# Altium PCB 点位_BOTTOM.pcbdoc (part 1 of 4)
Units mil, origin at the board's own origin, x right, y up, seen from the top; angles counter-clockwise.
Board outline 5102.8 x 4152 mil, 8 copper layers (Top Layer, GND1, 内层2, VCC, 内层4, Inner5, GND2, Bottom Layer); 209 components, 325 nets, 527 pads, 1119 vias.
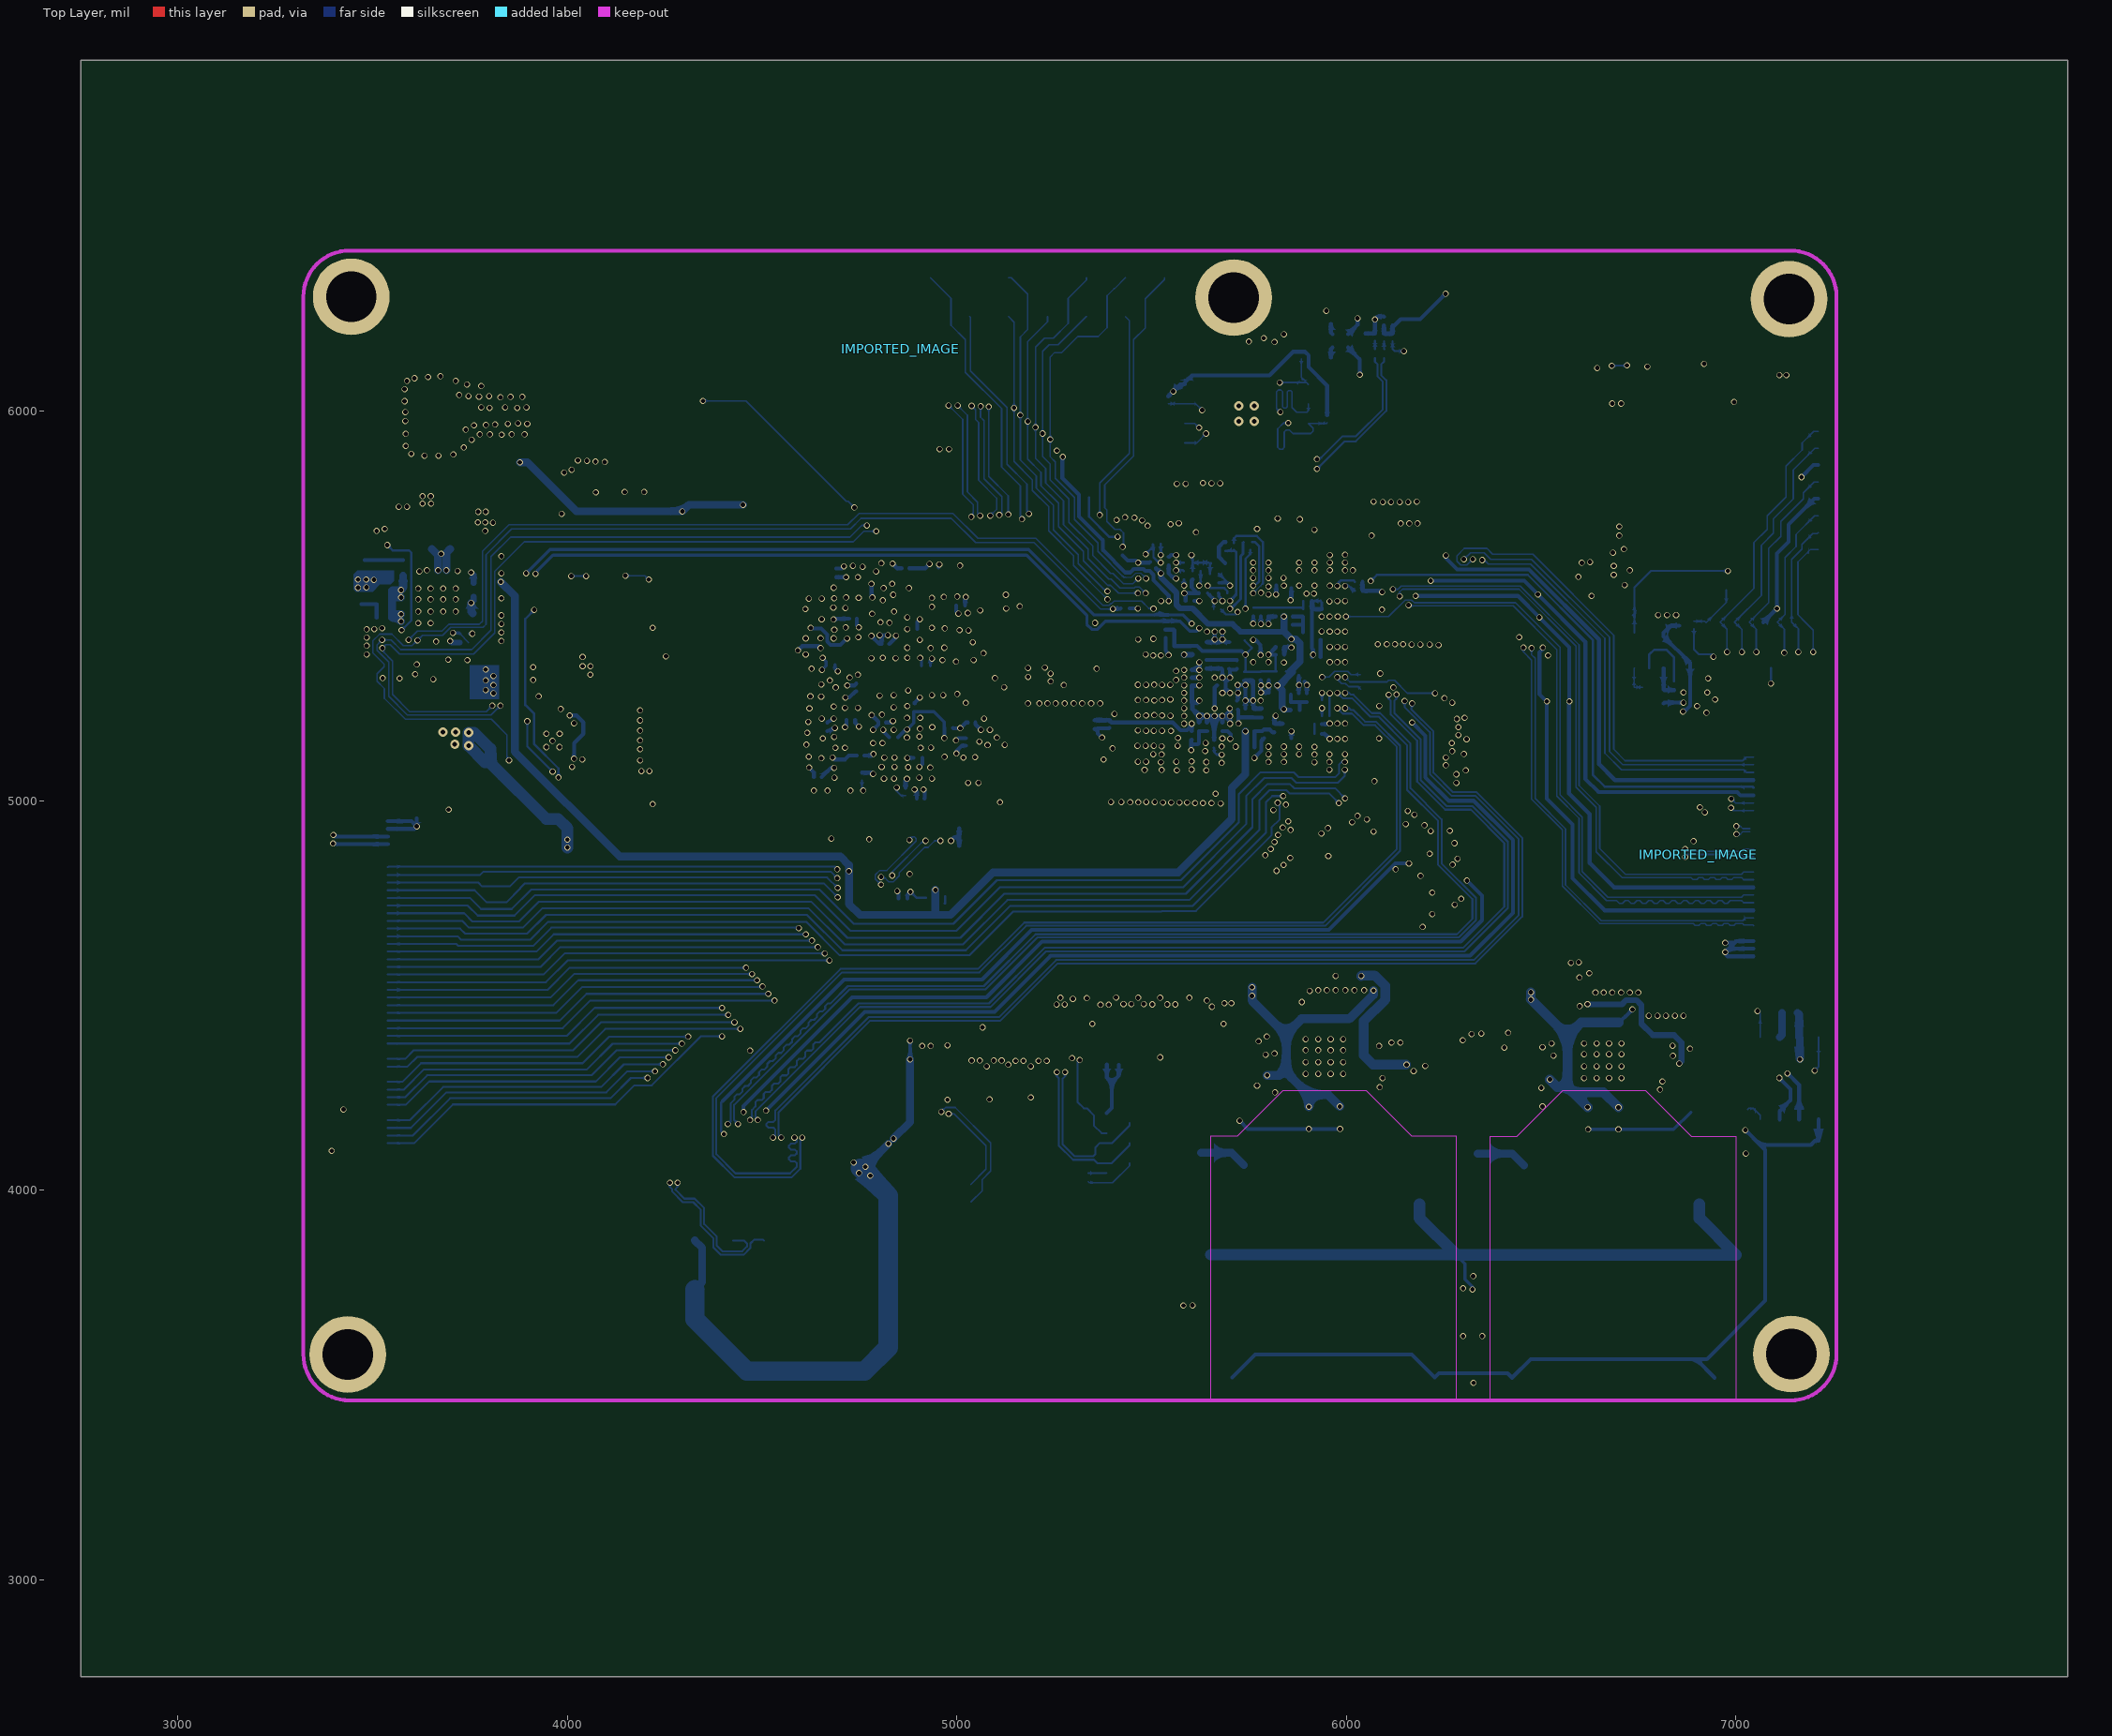
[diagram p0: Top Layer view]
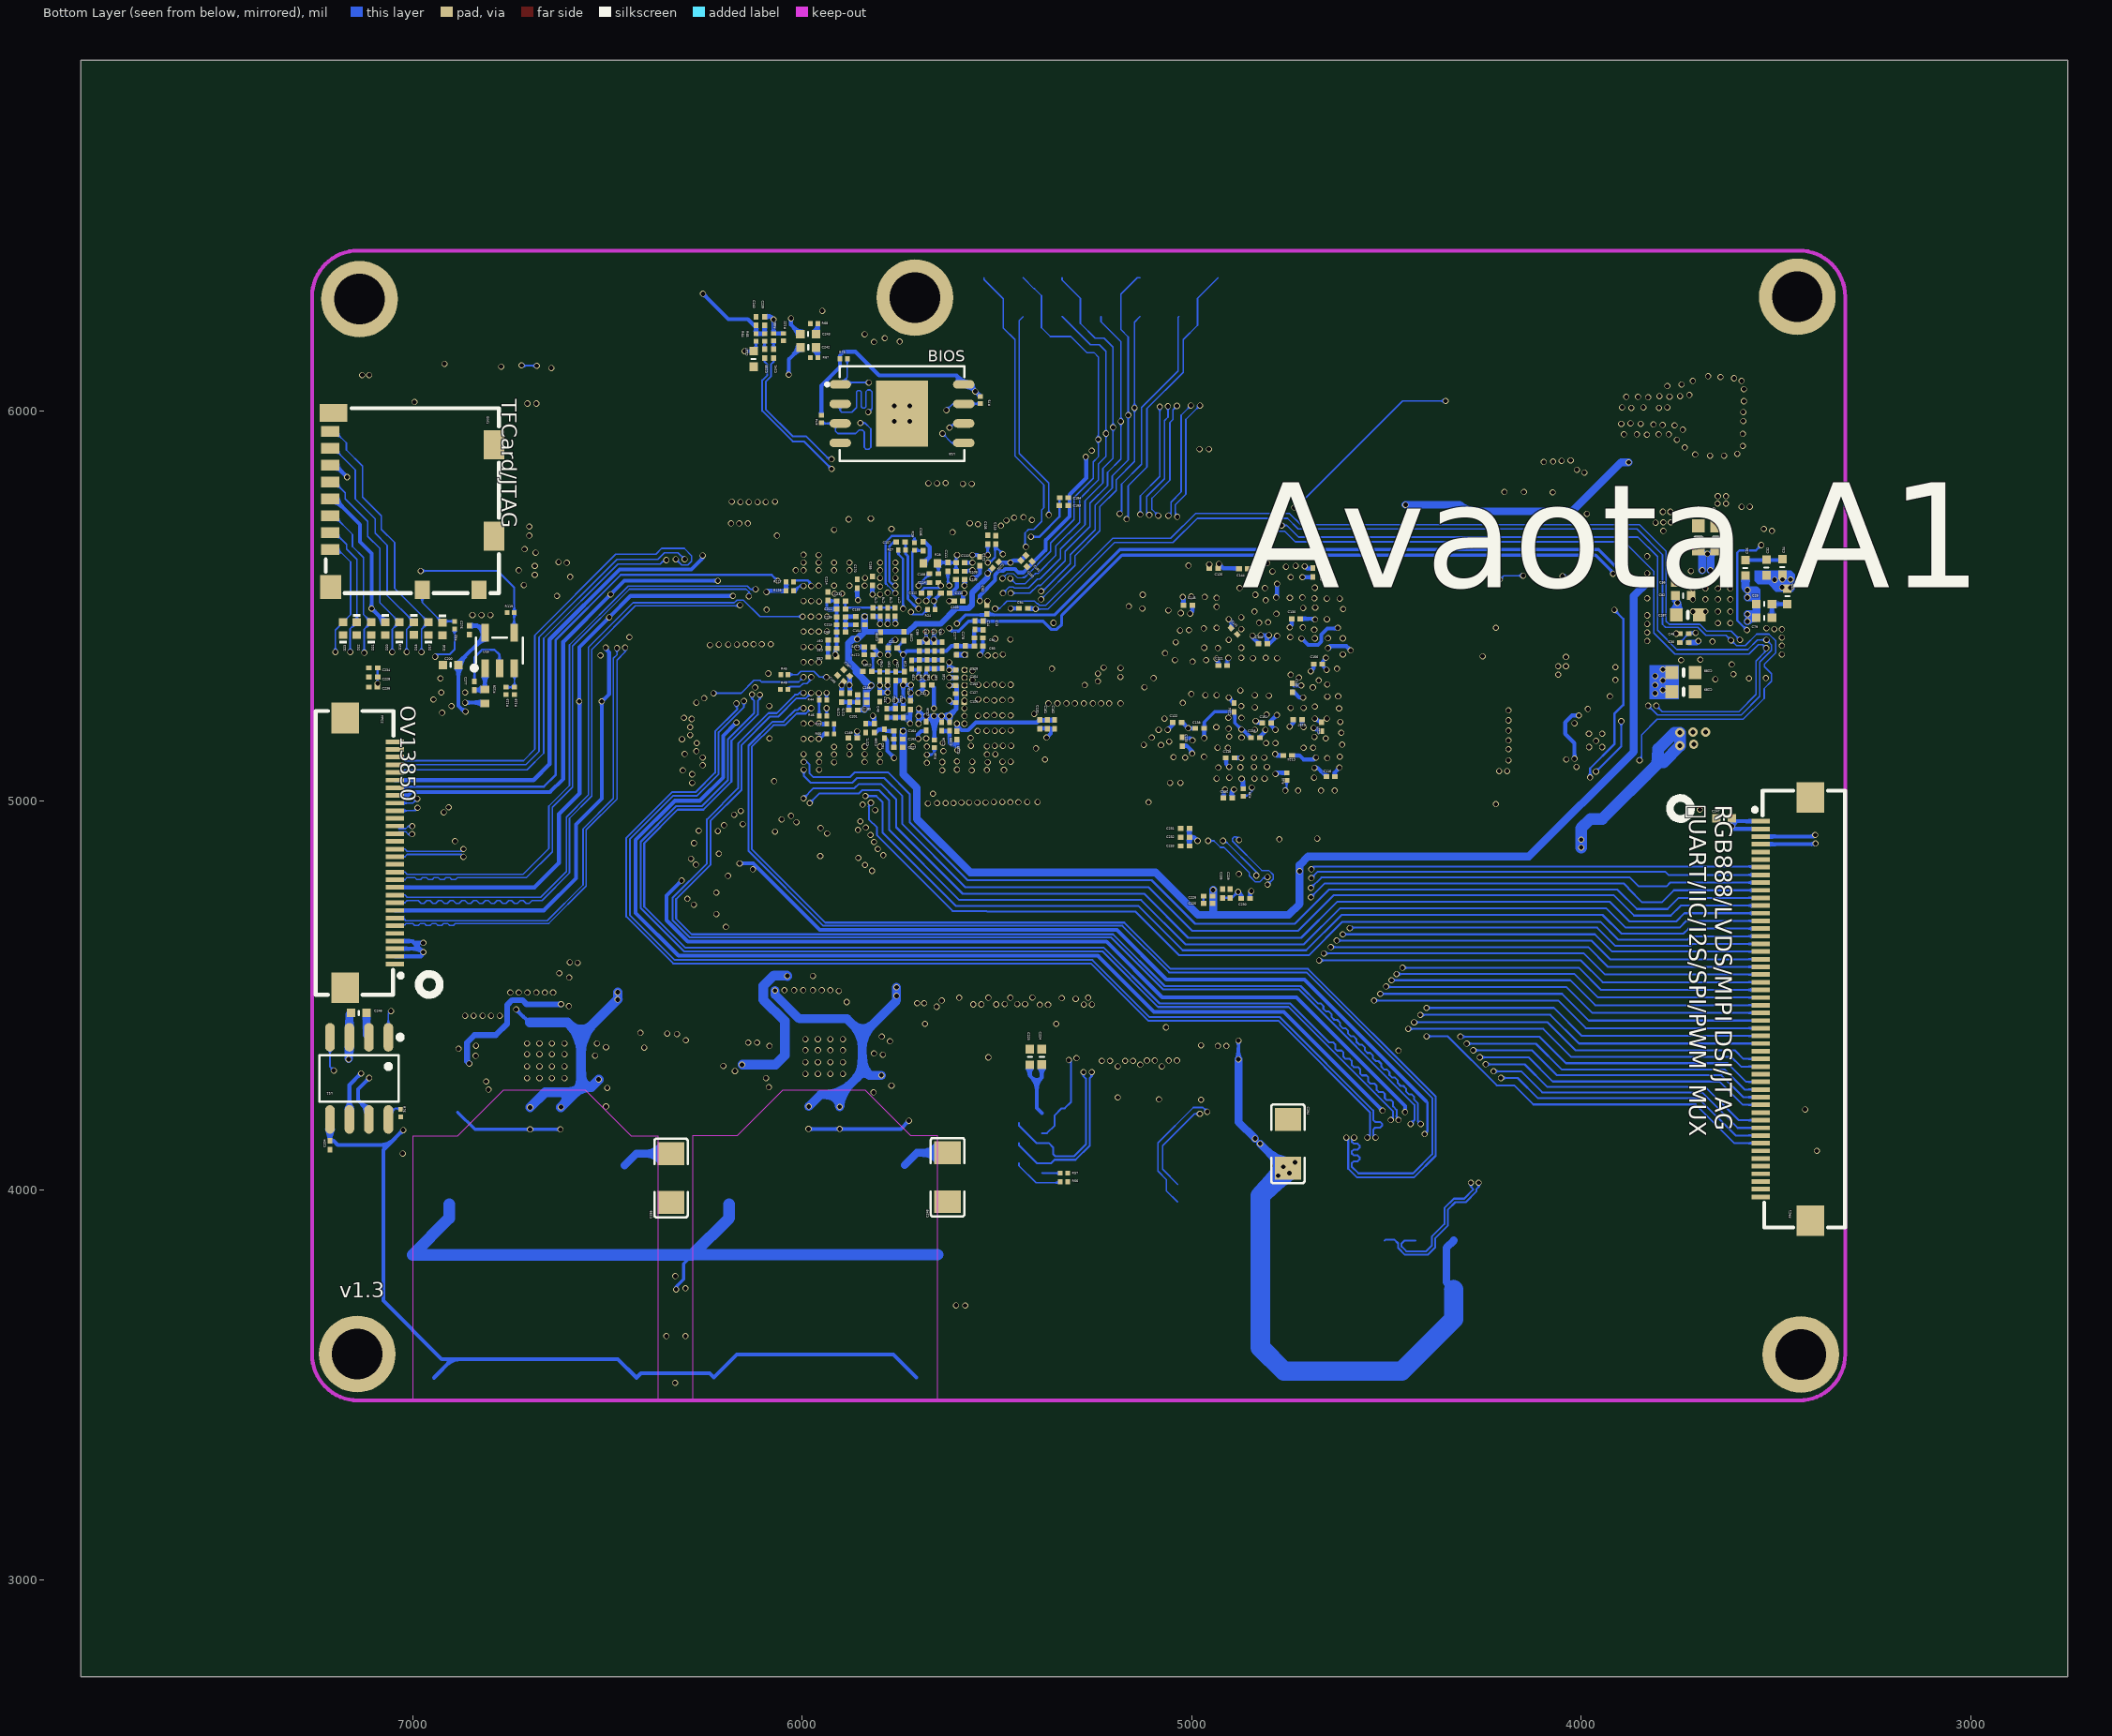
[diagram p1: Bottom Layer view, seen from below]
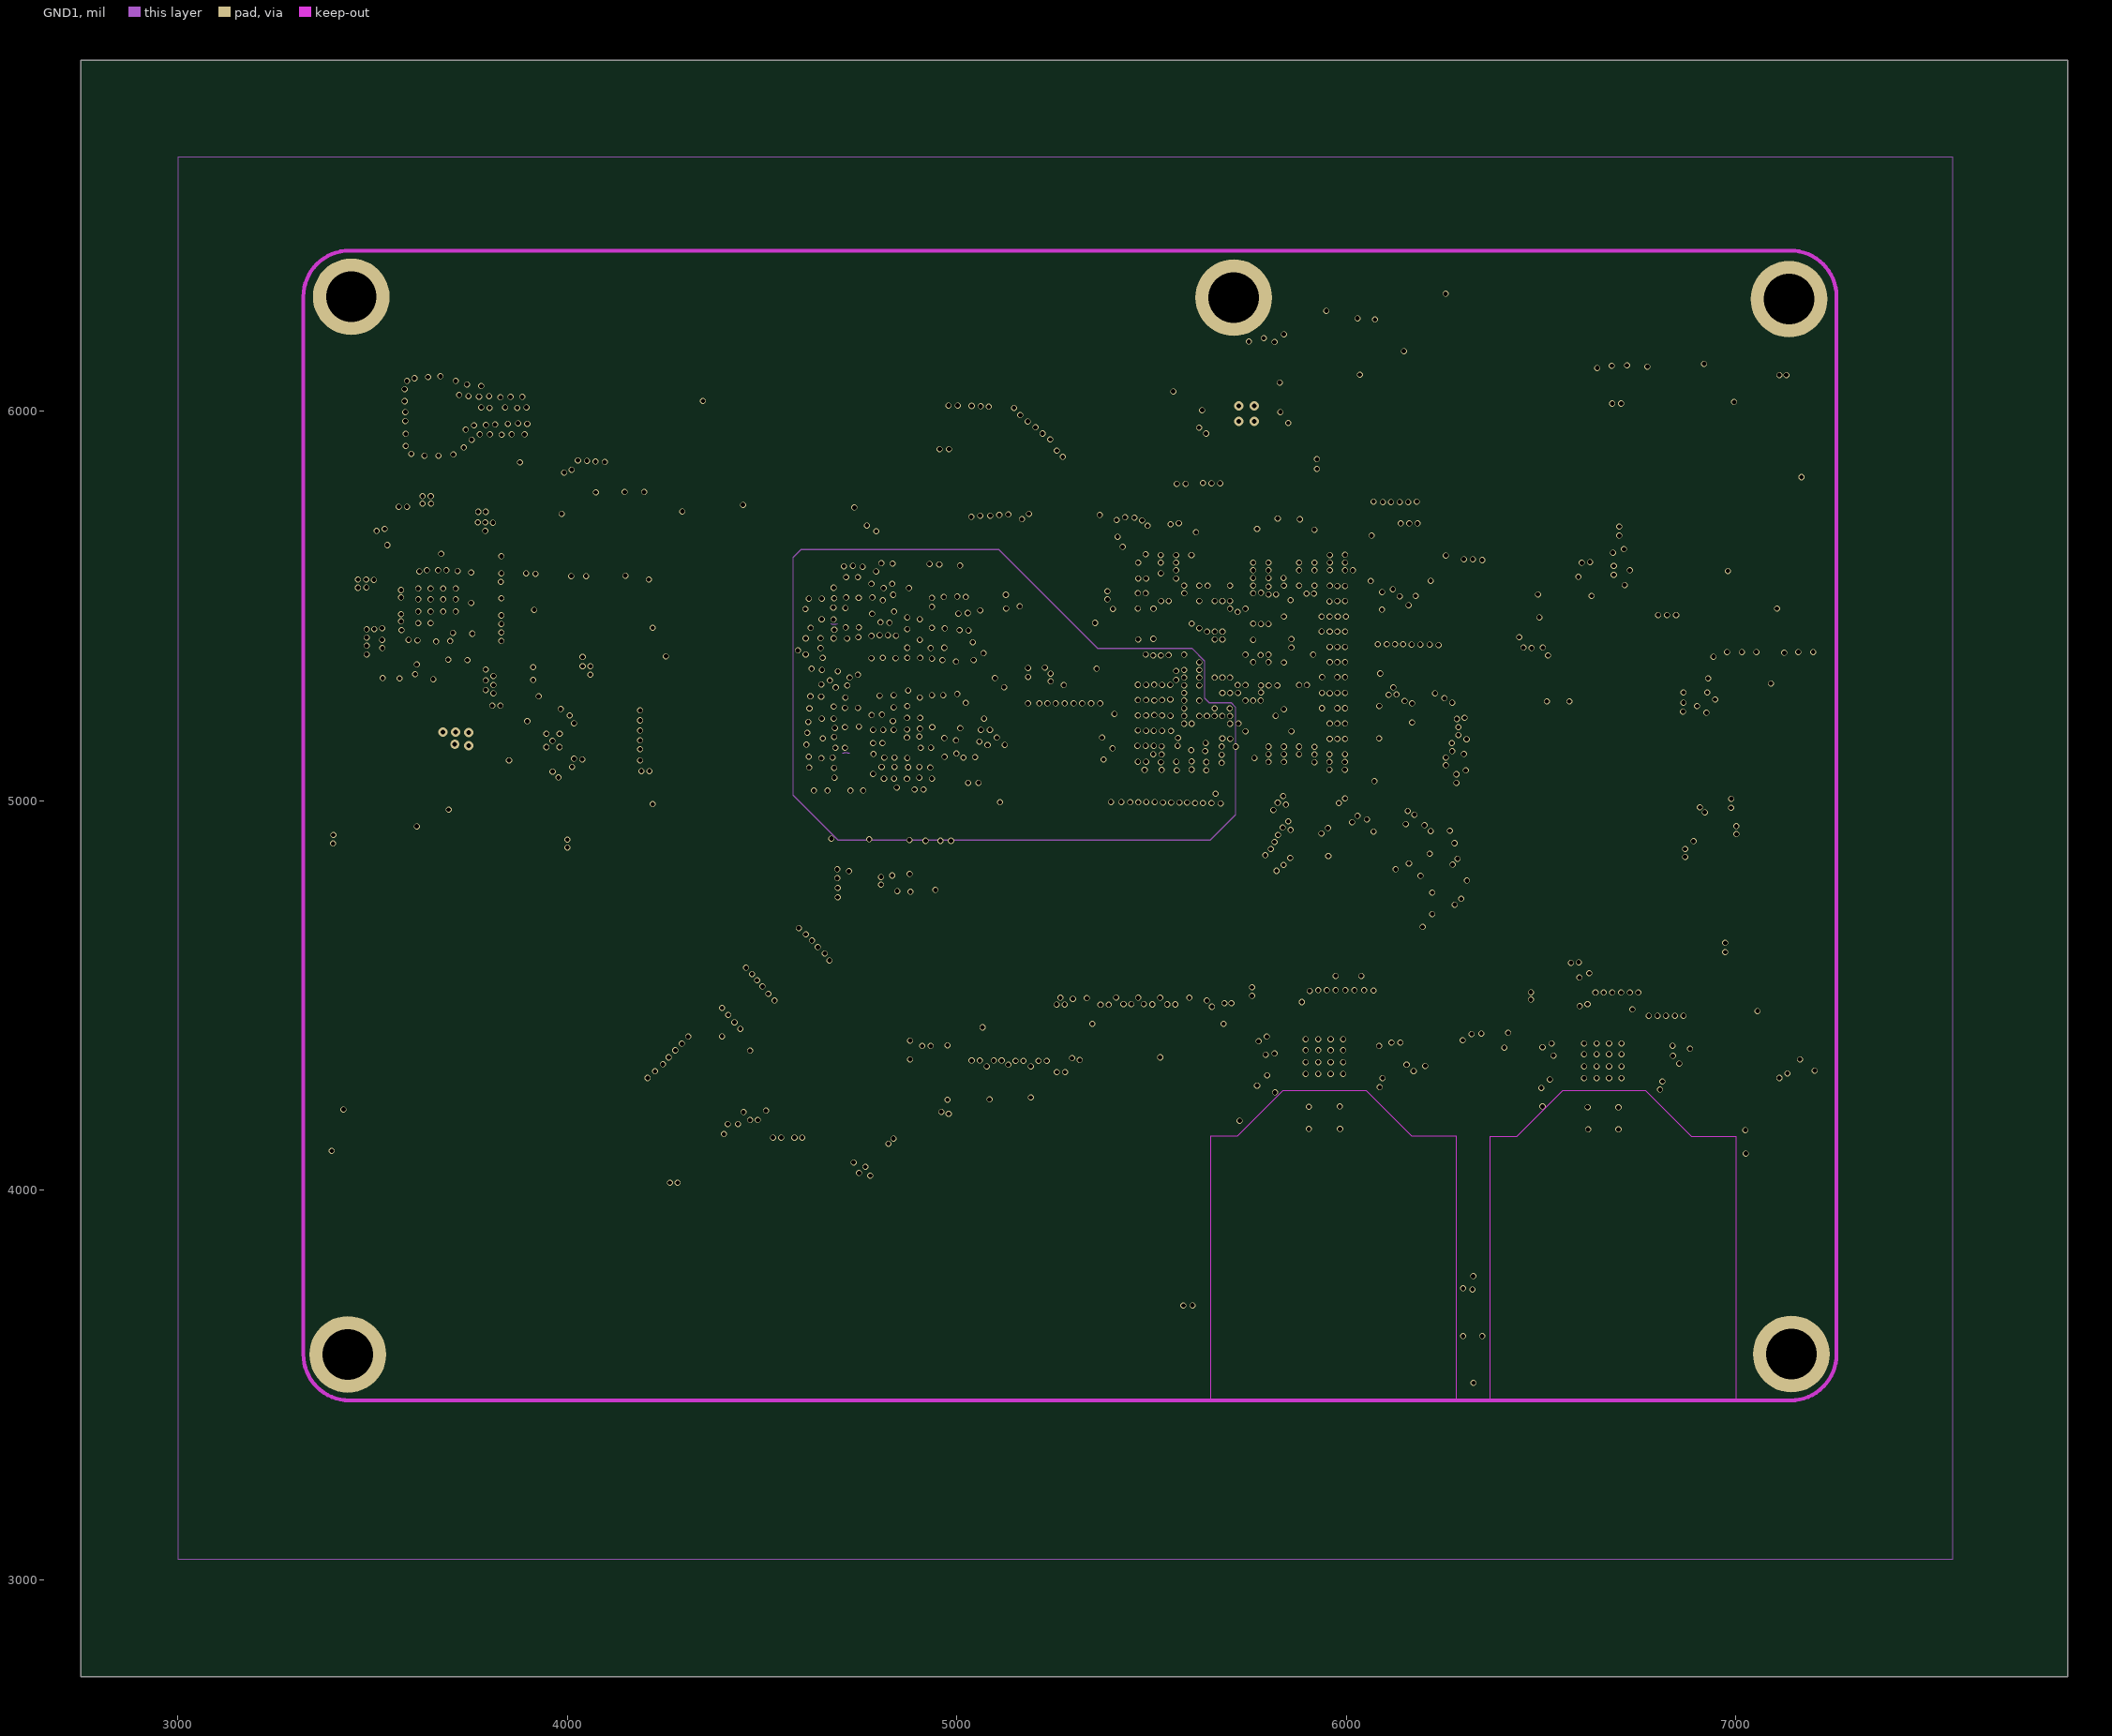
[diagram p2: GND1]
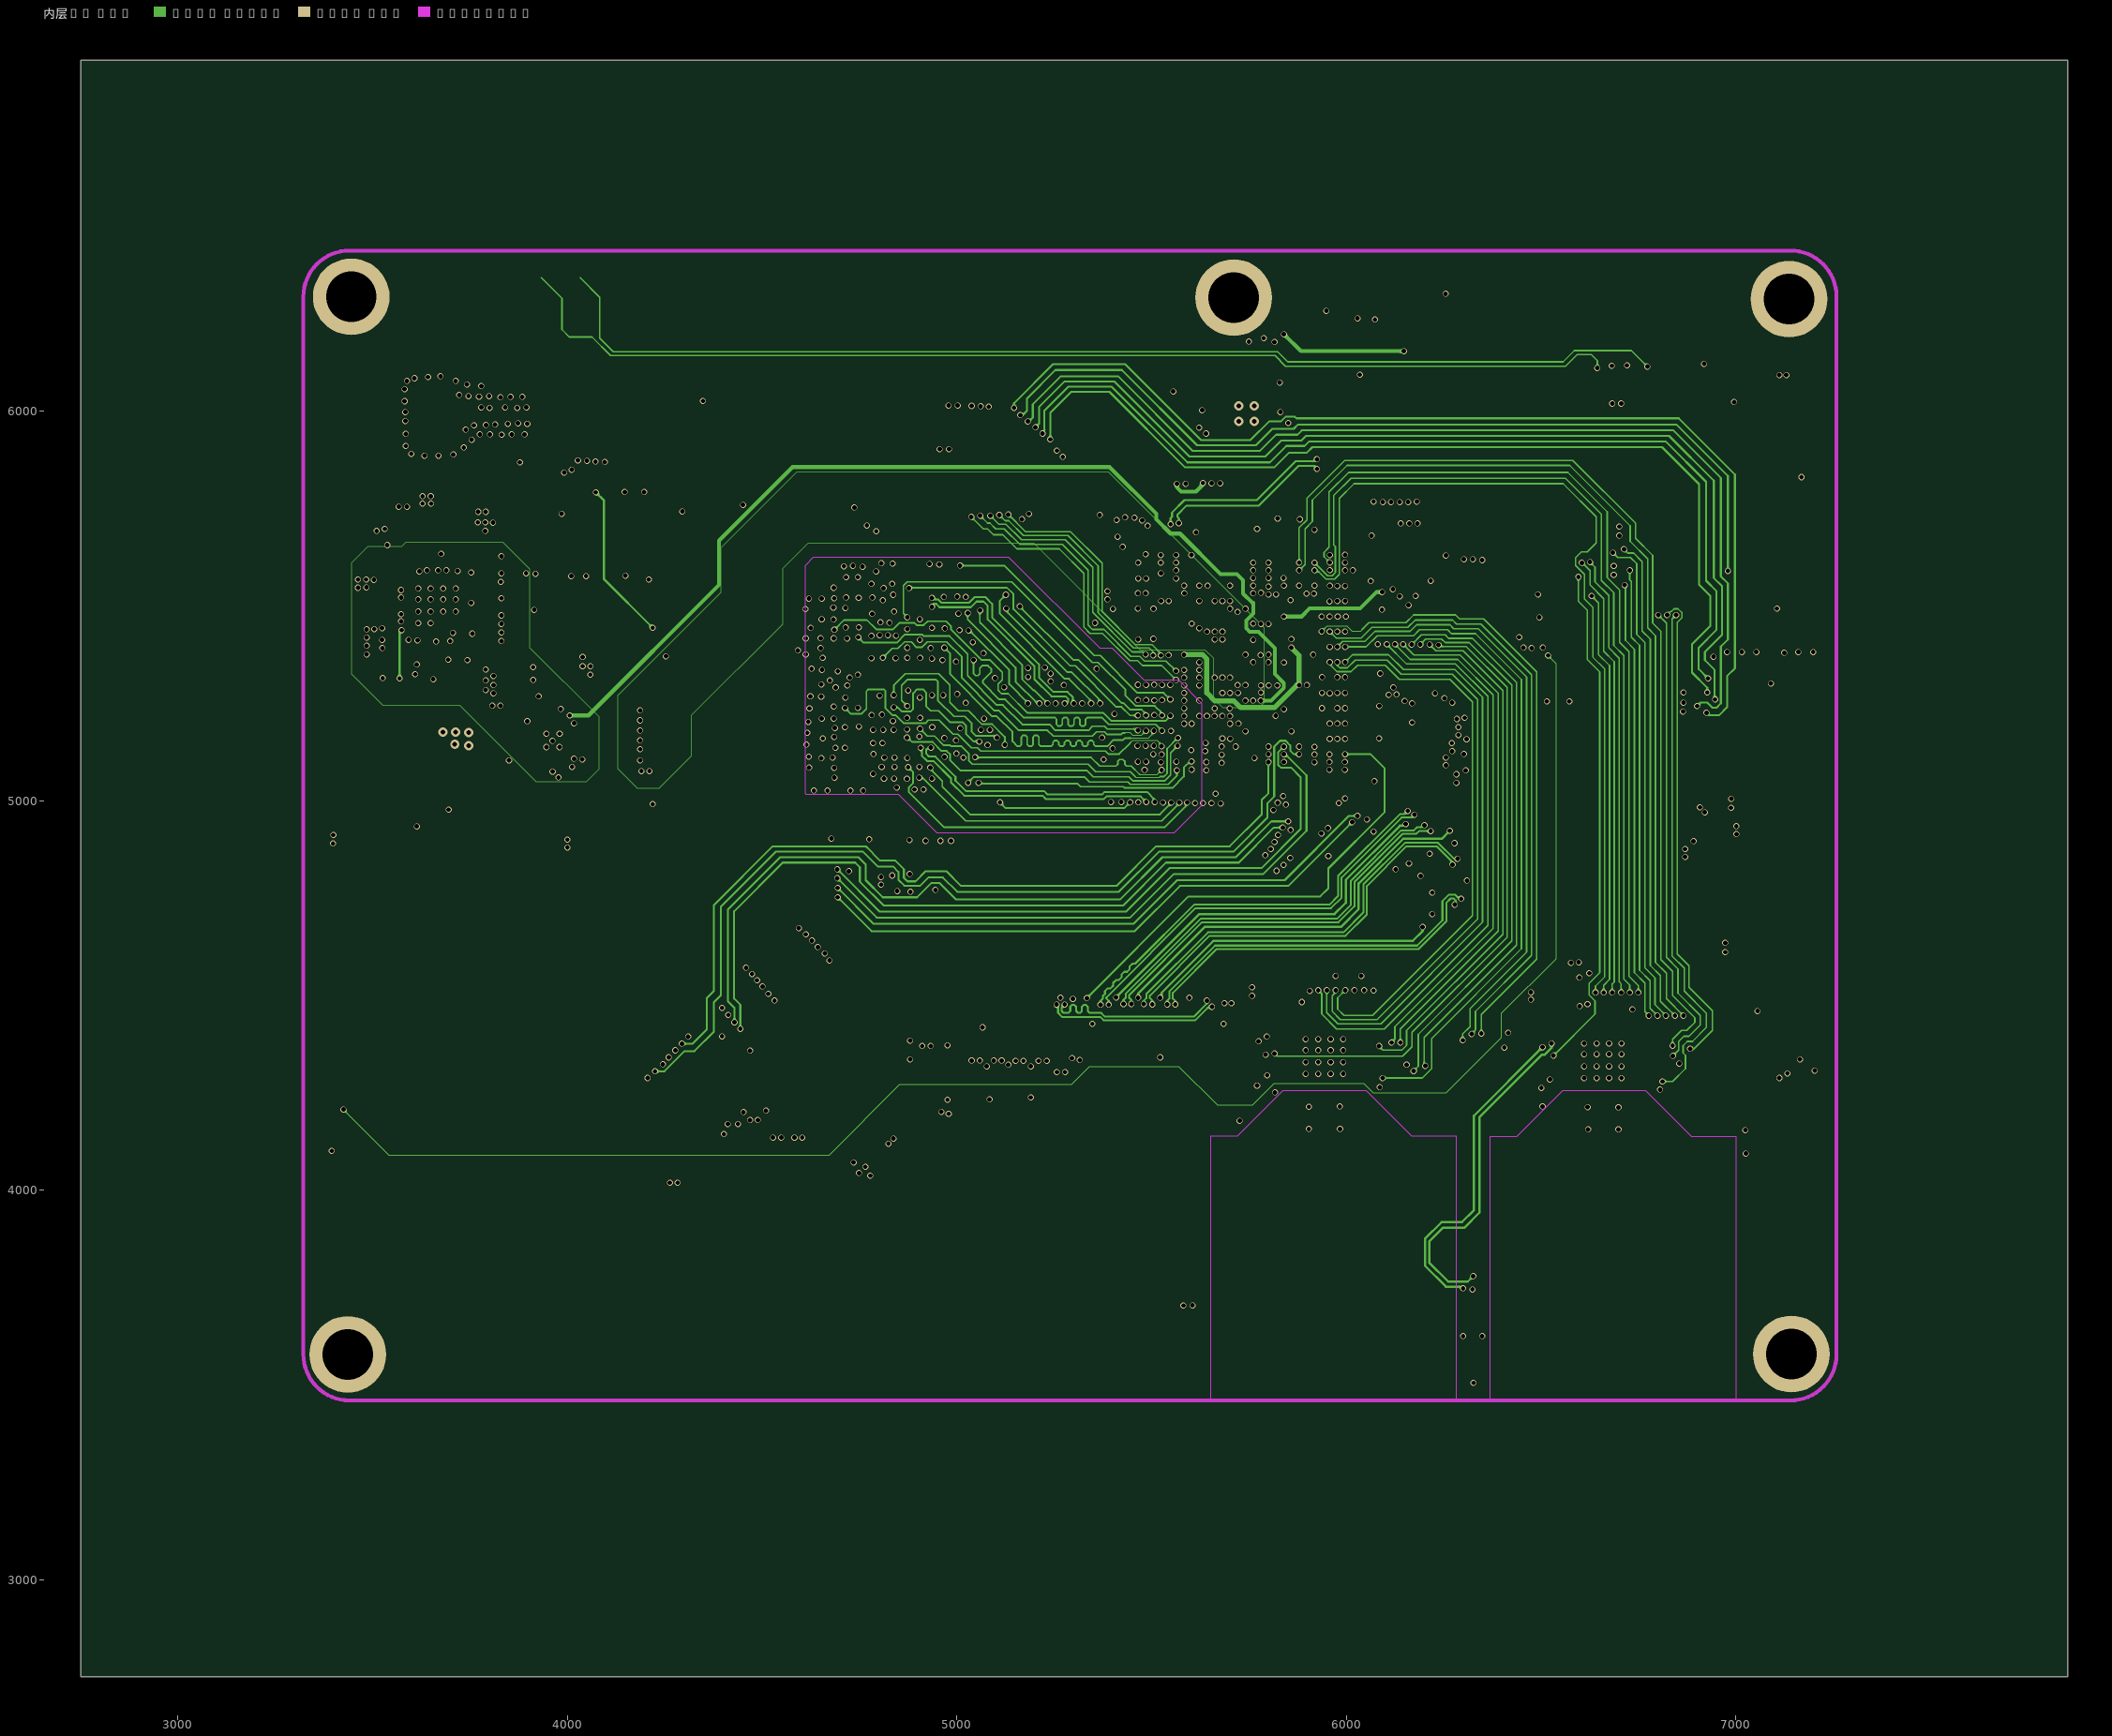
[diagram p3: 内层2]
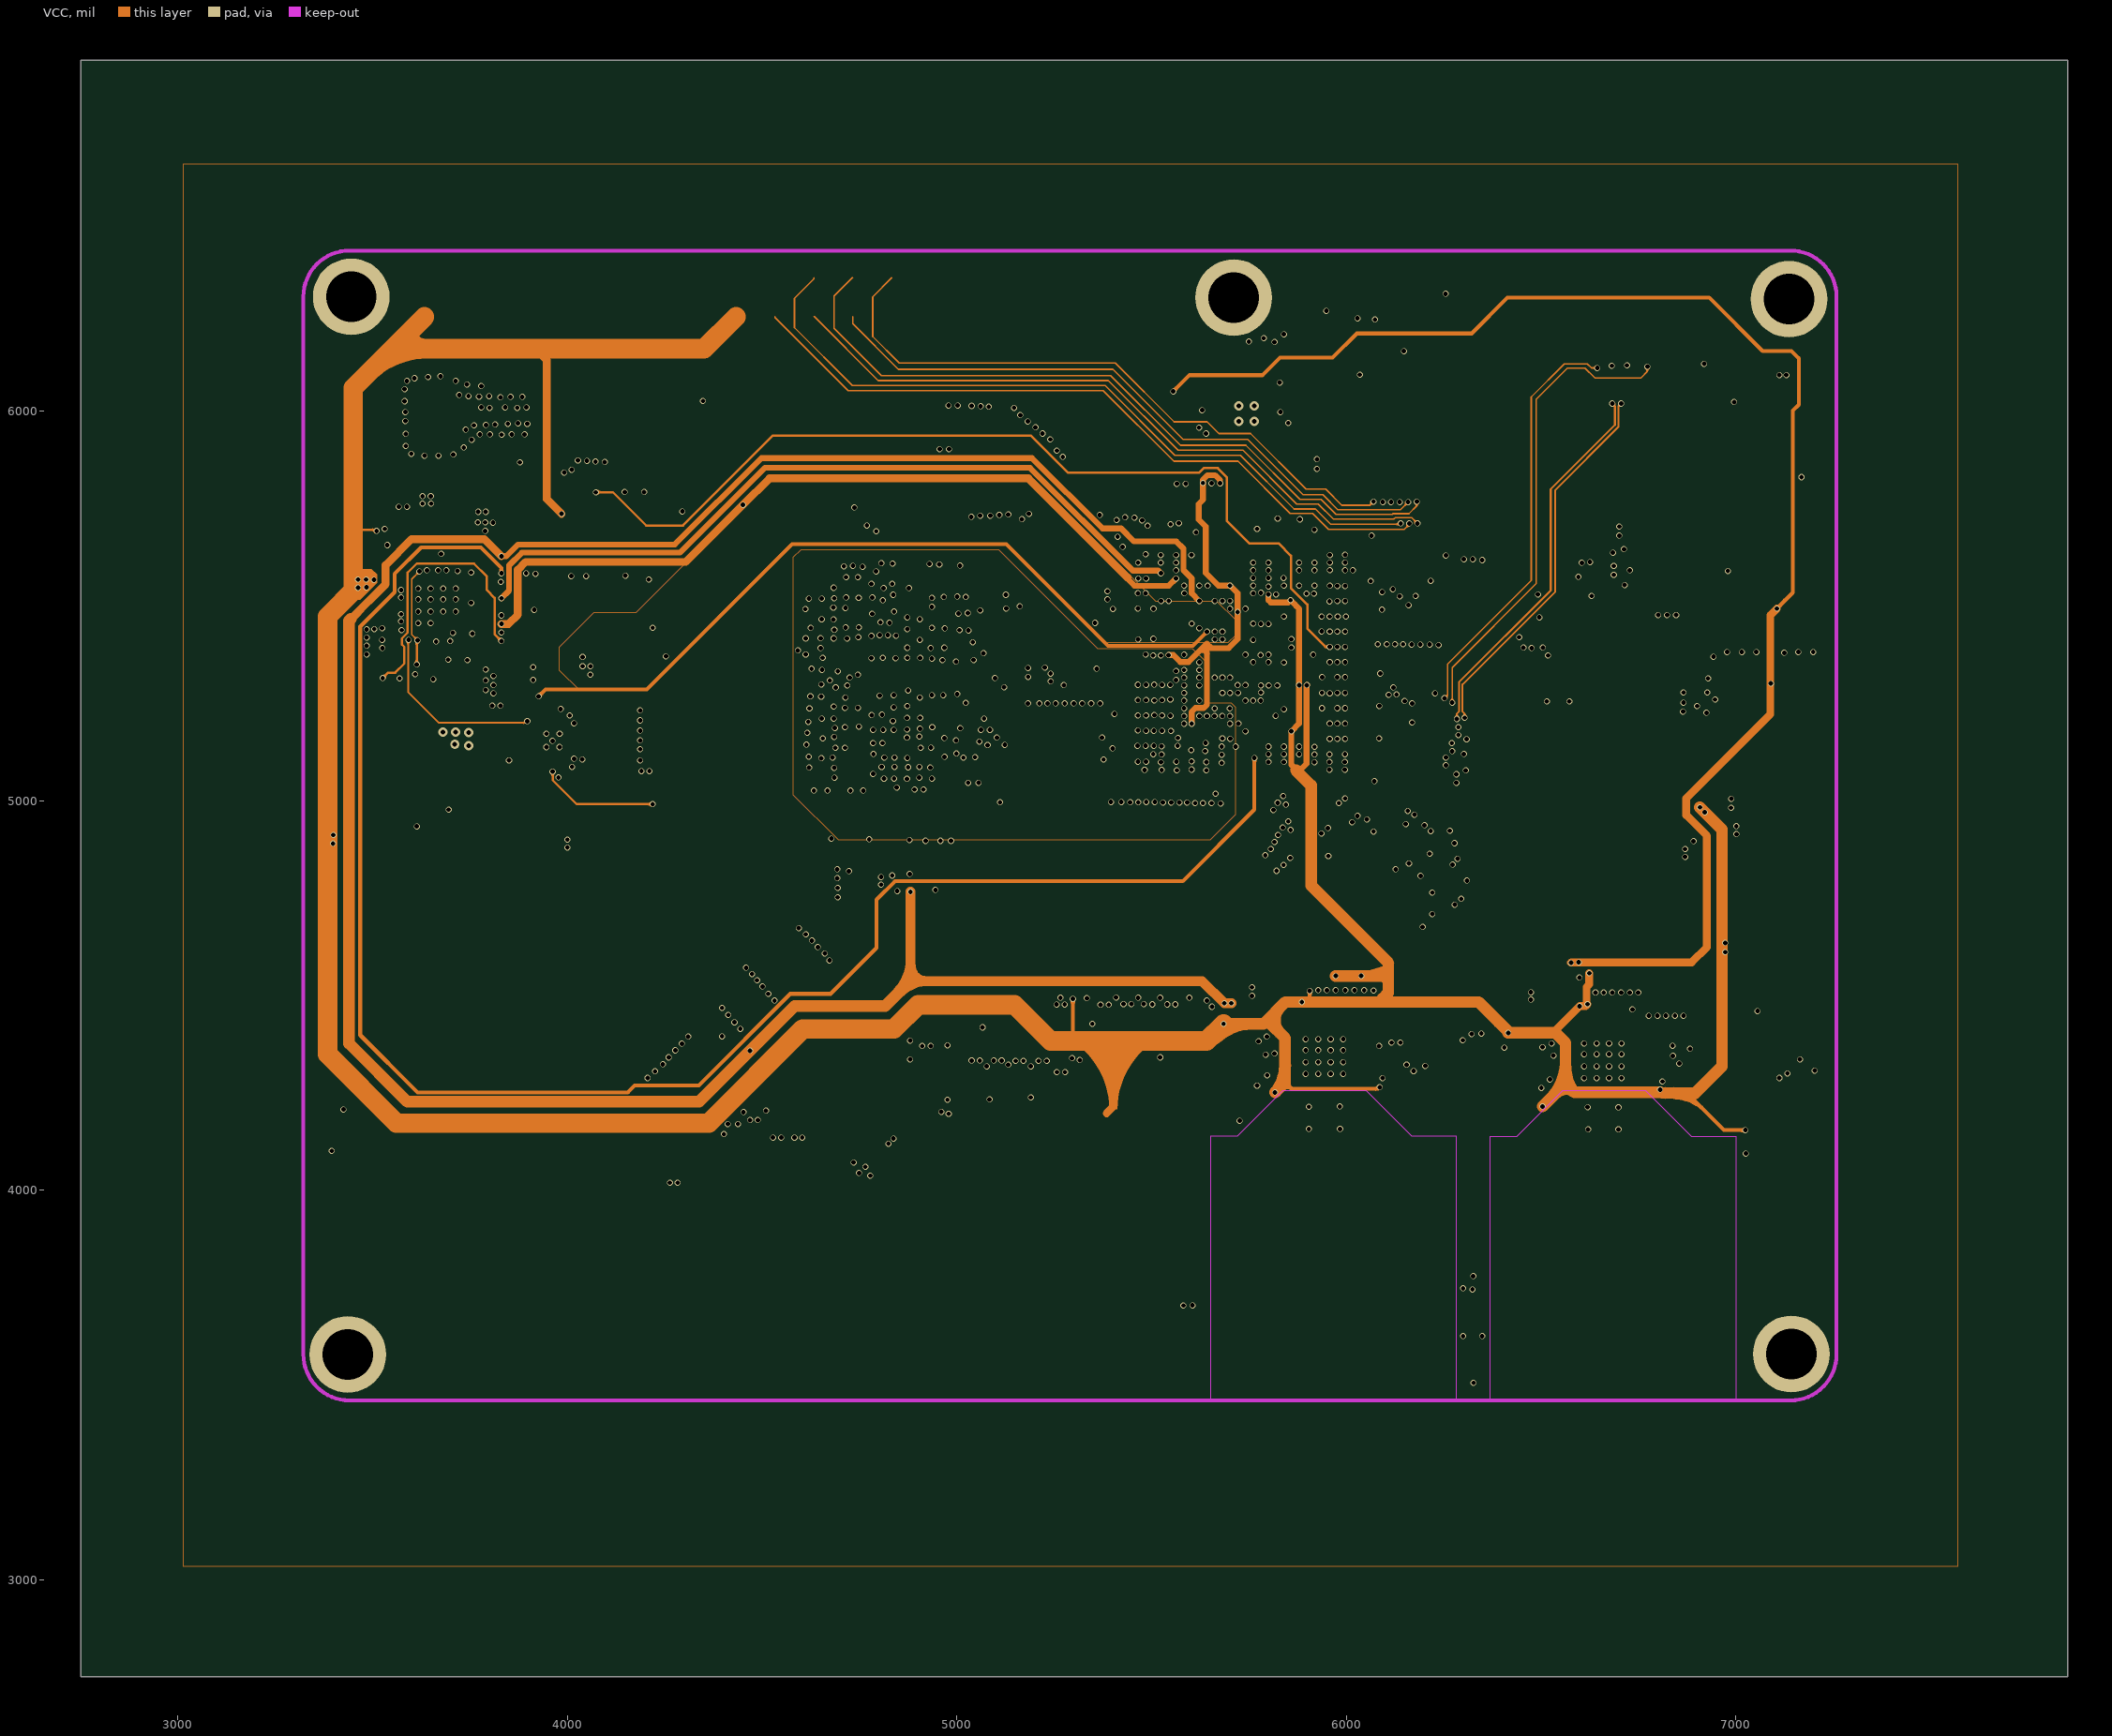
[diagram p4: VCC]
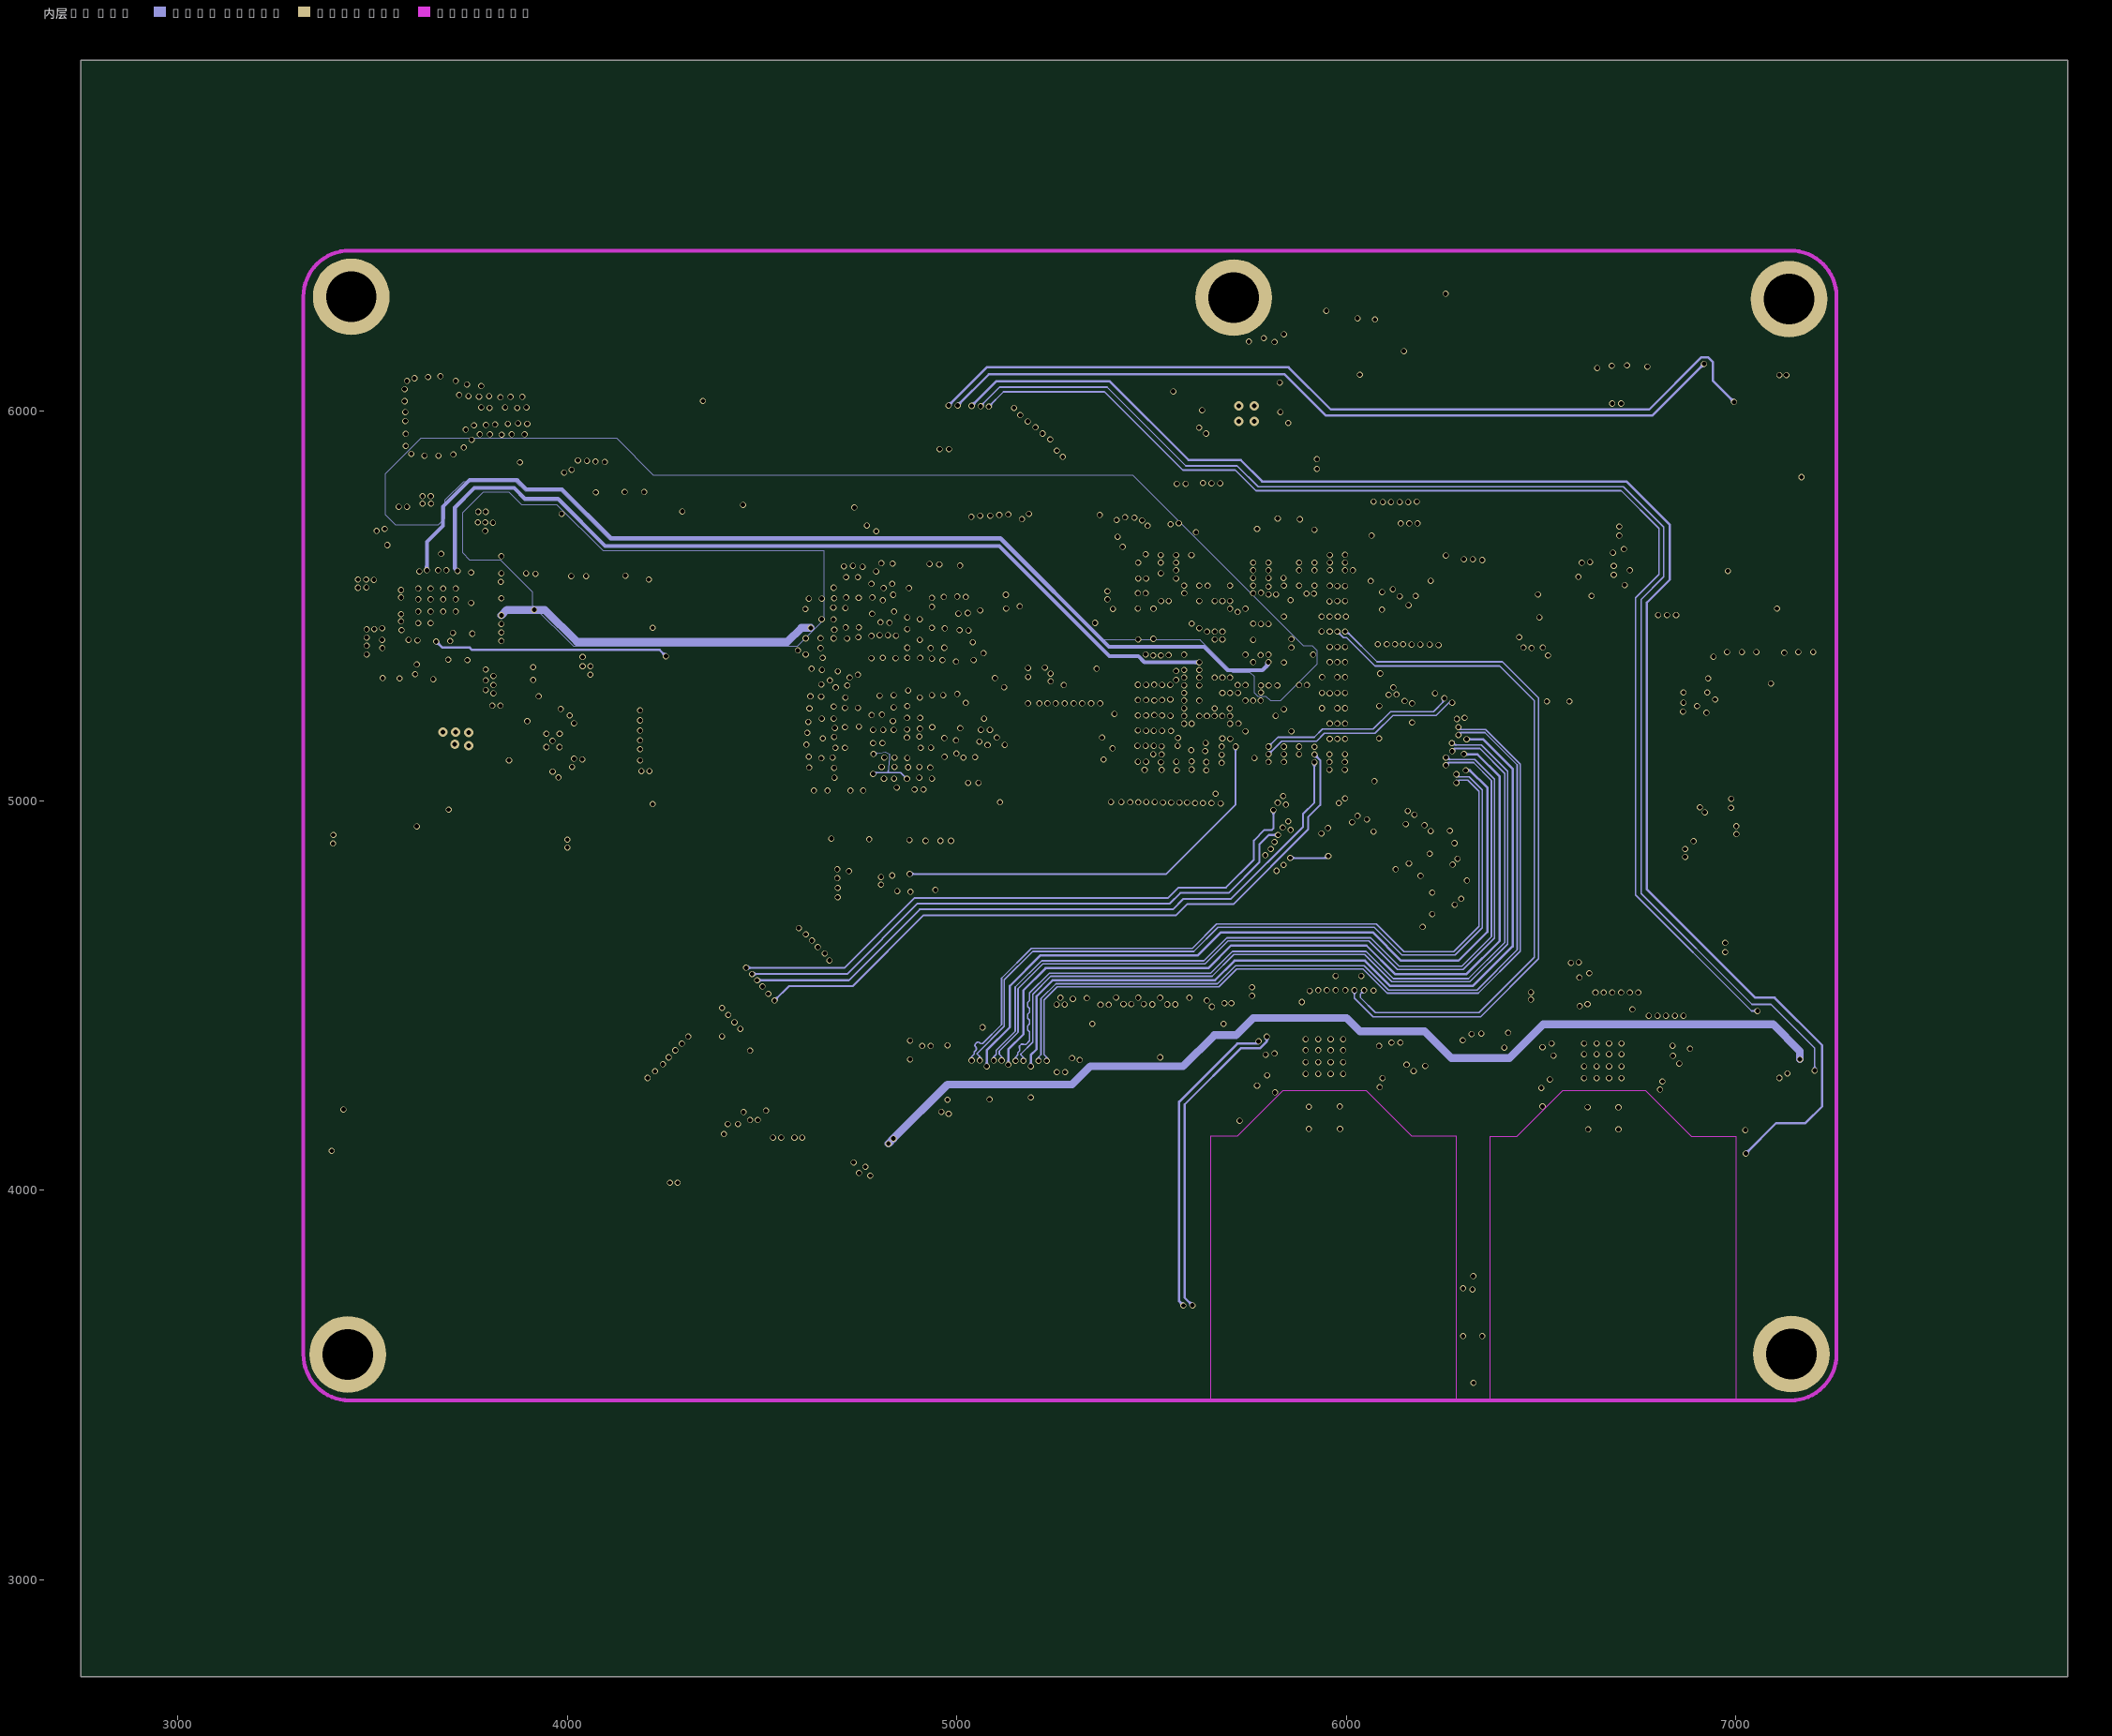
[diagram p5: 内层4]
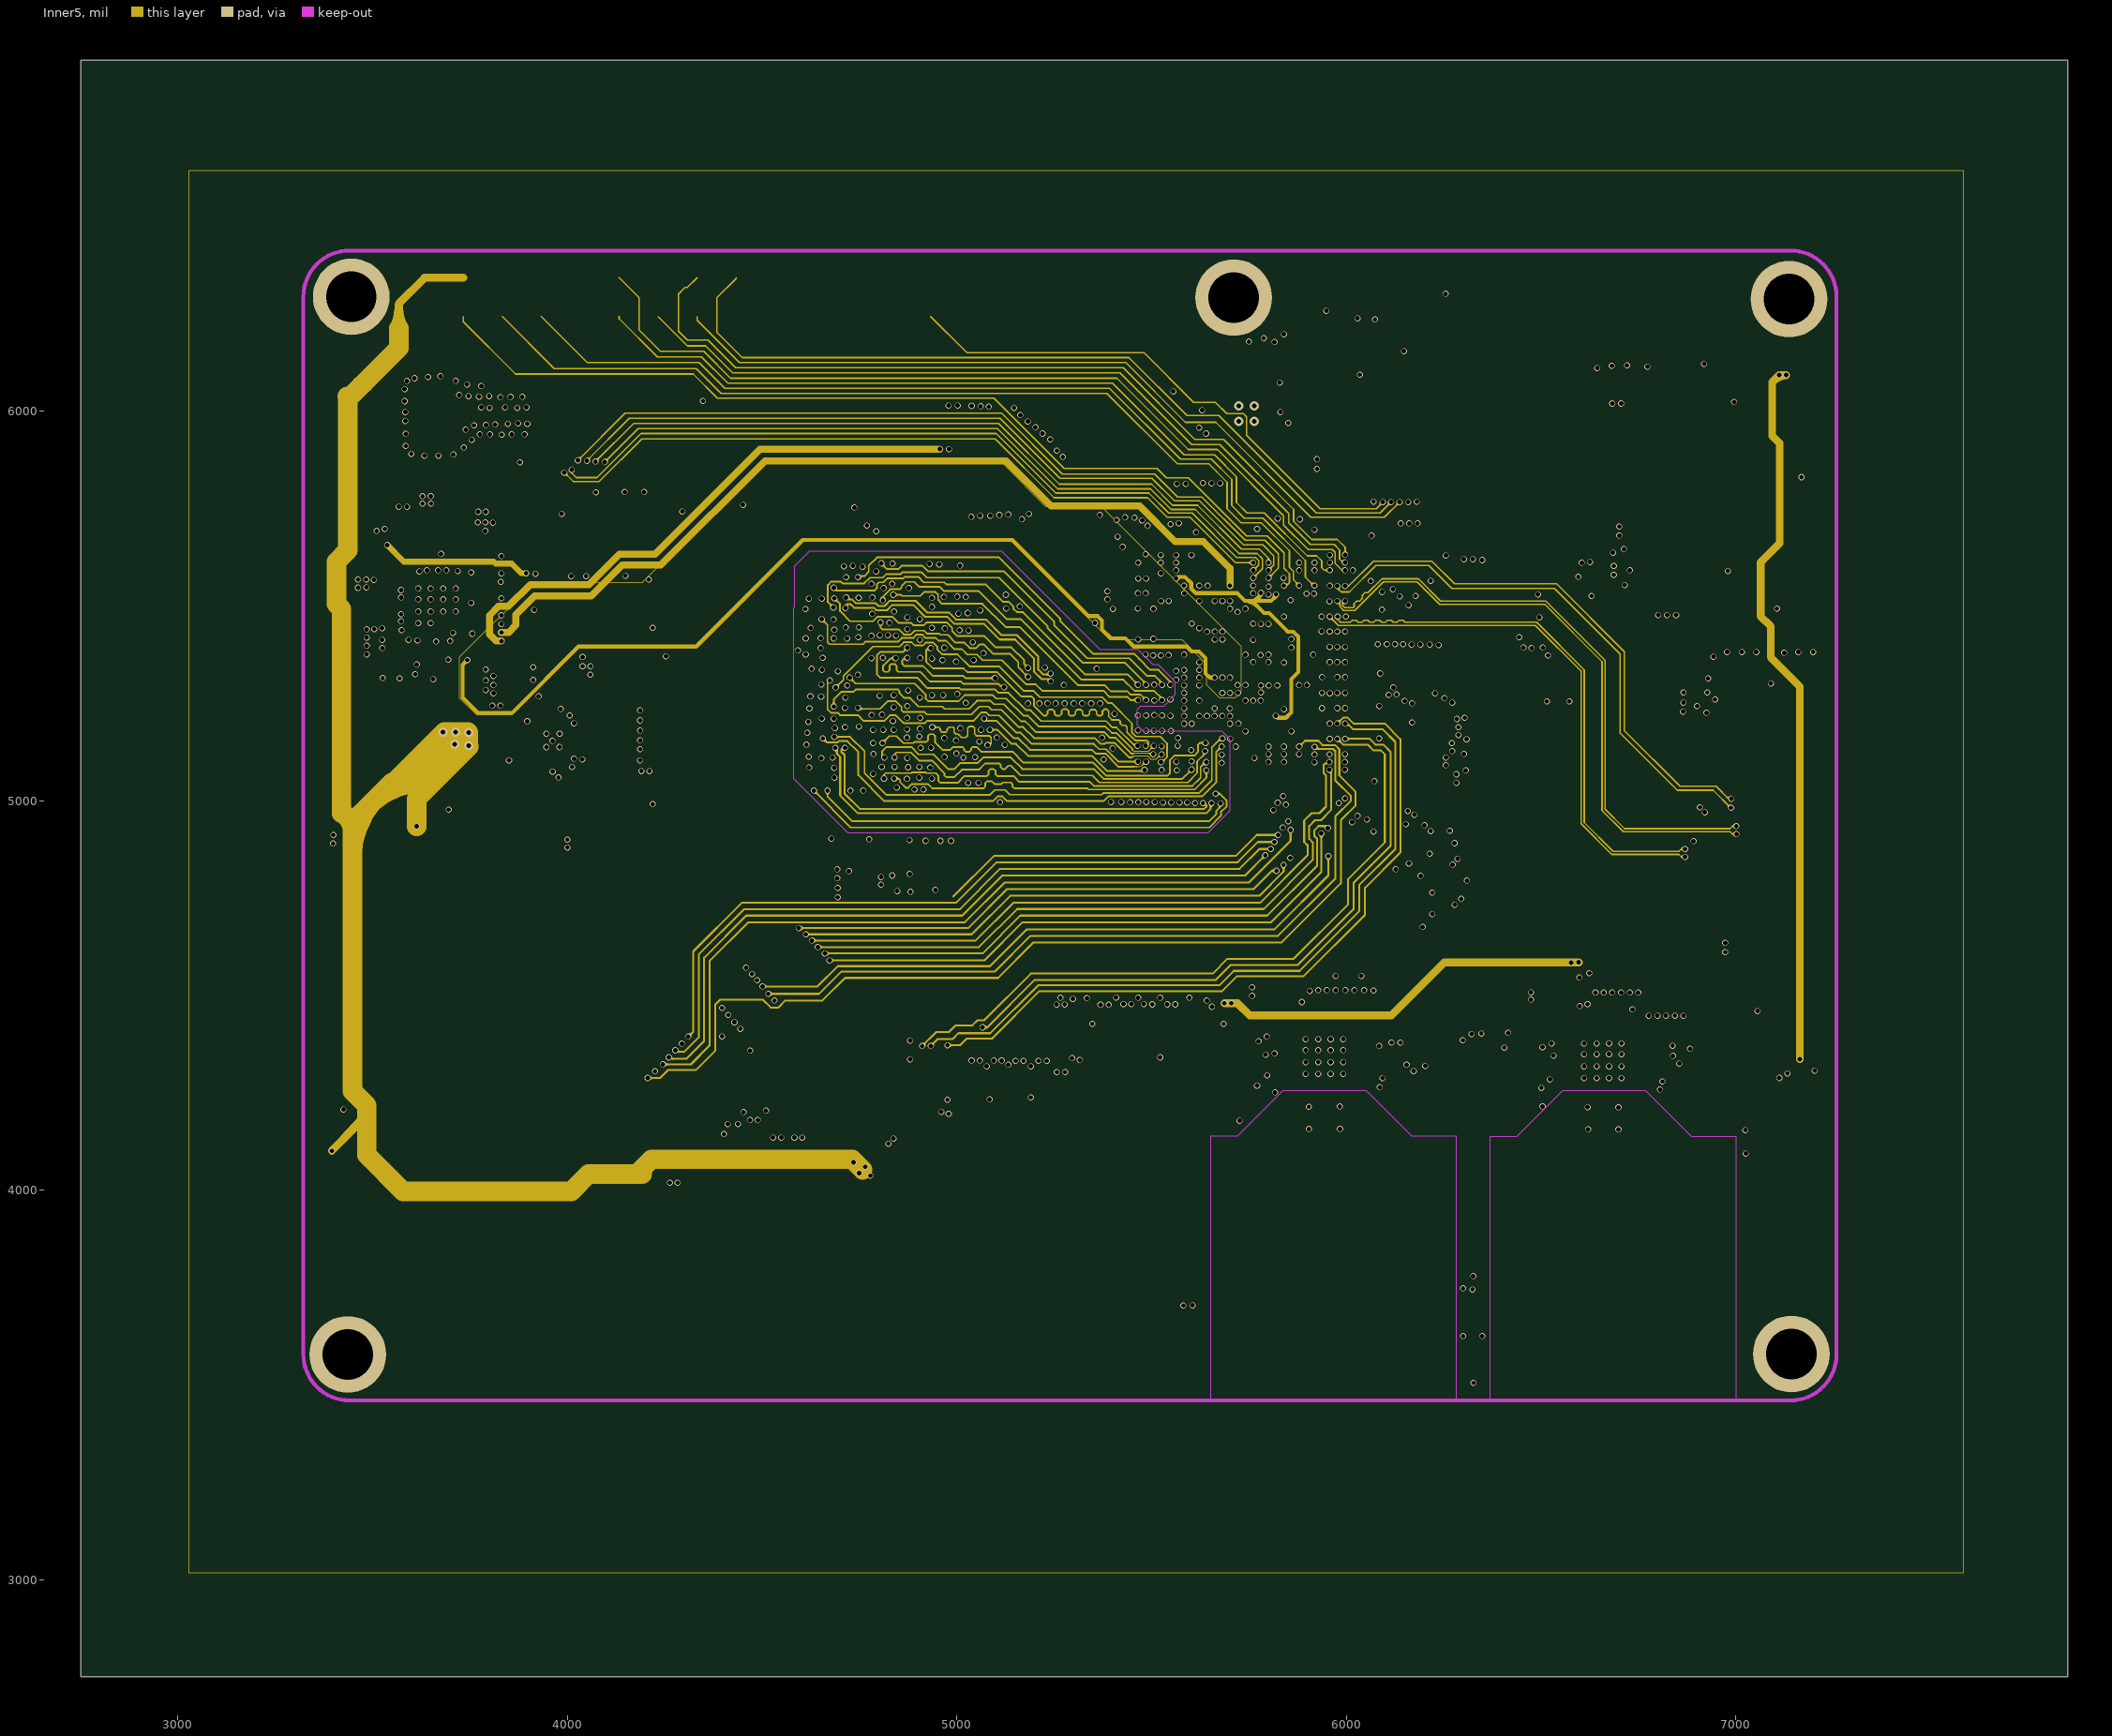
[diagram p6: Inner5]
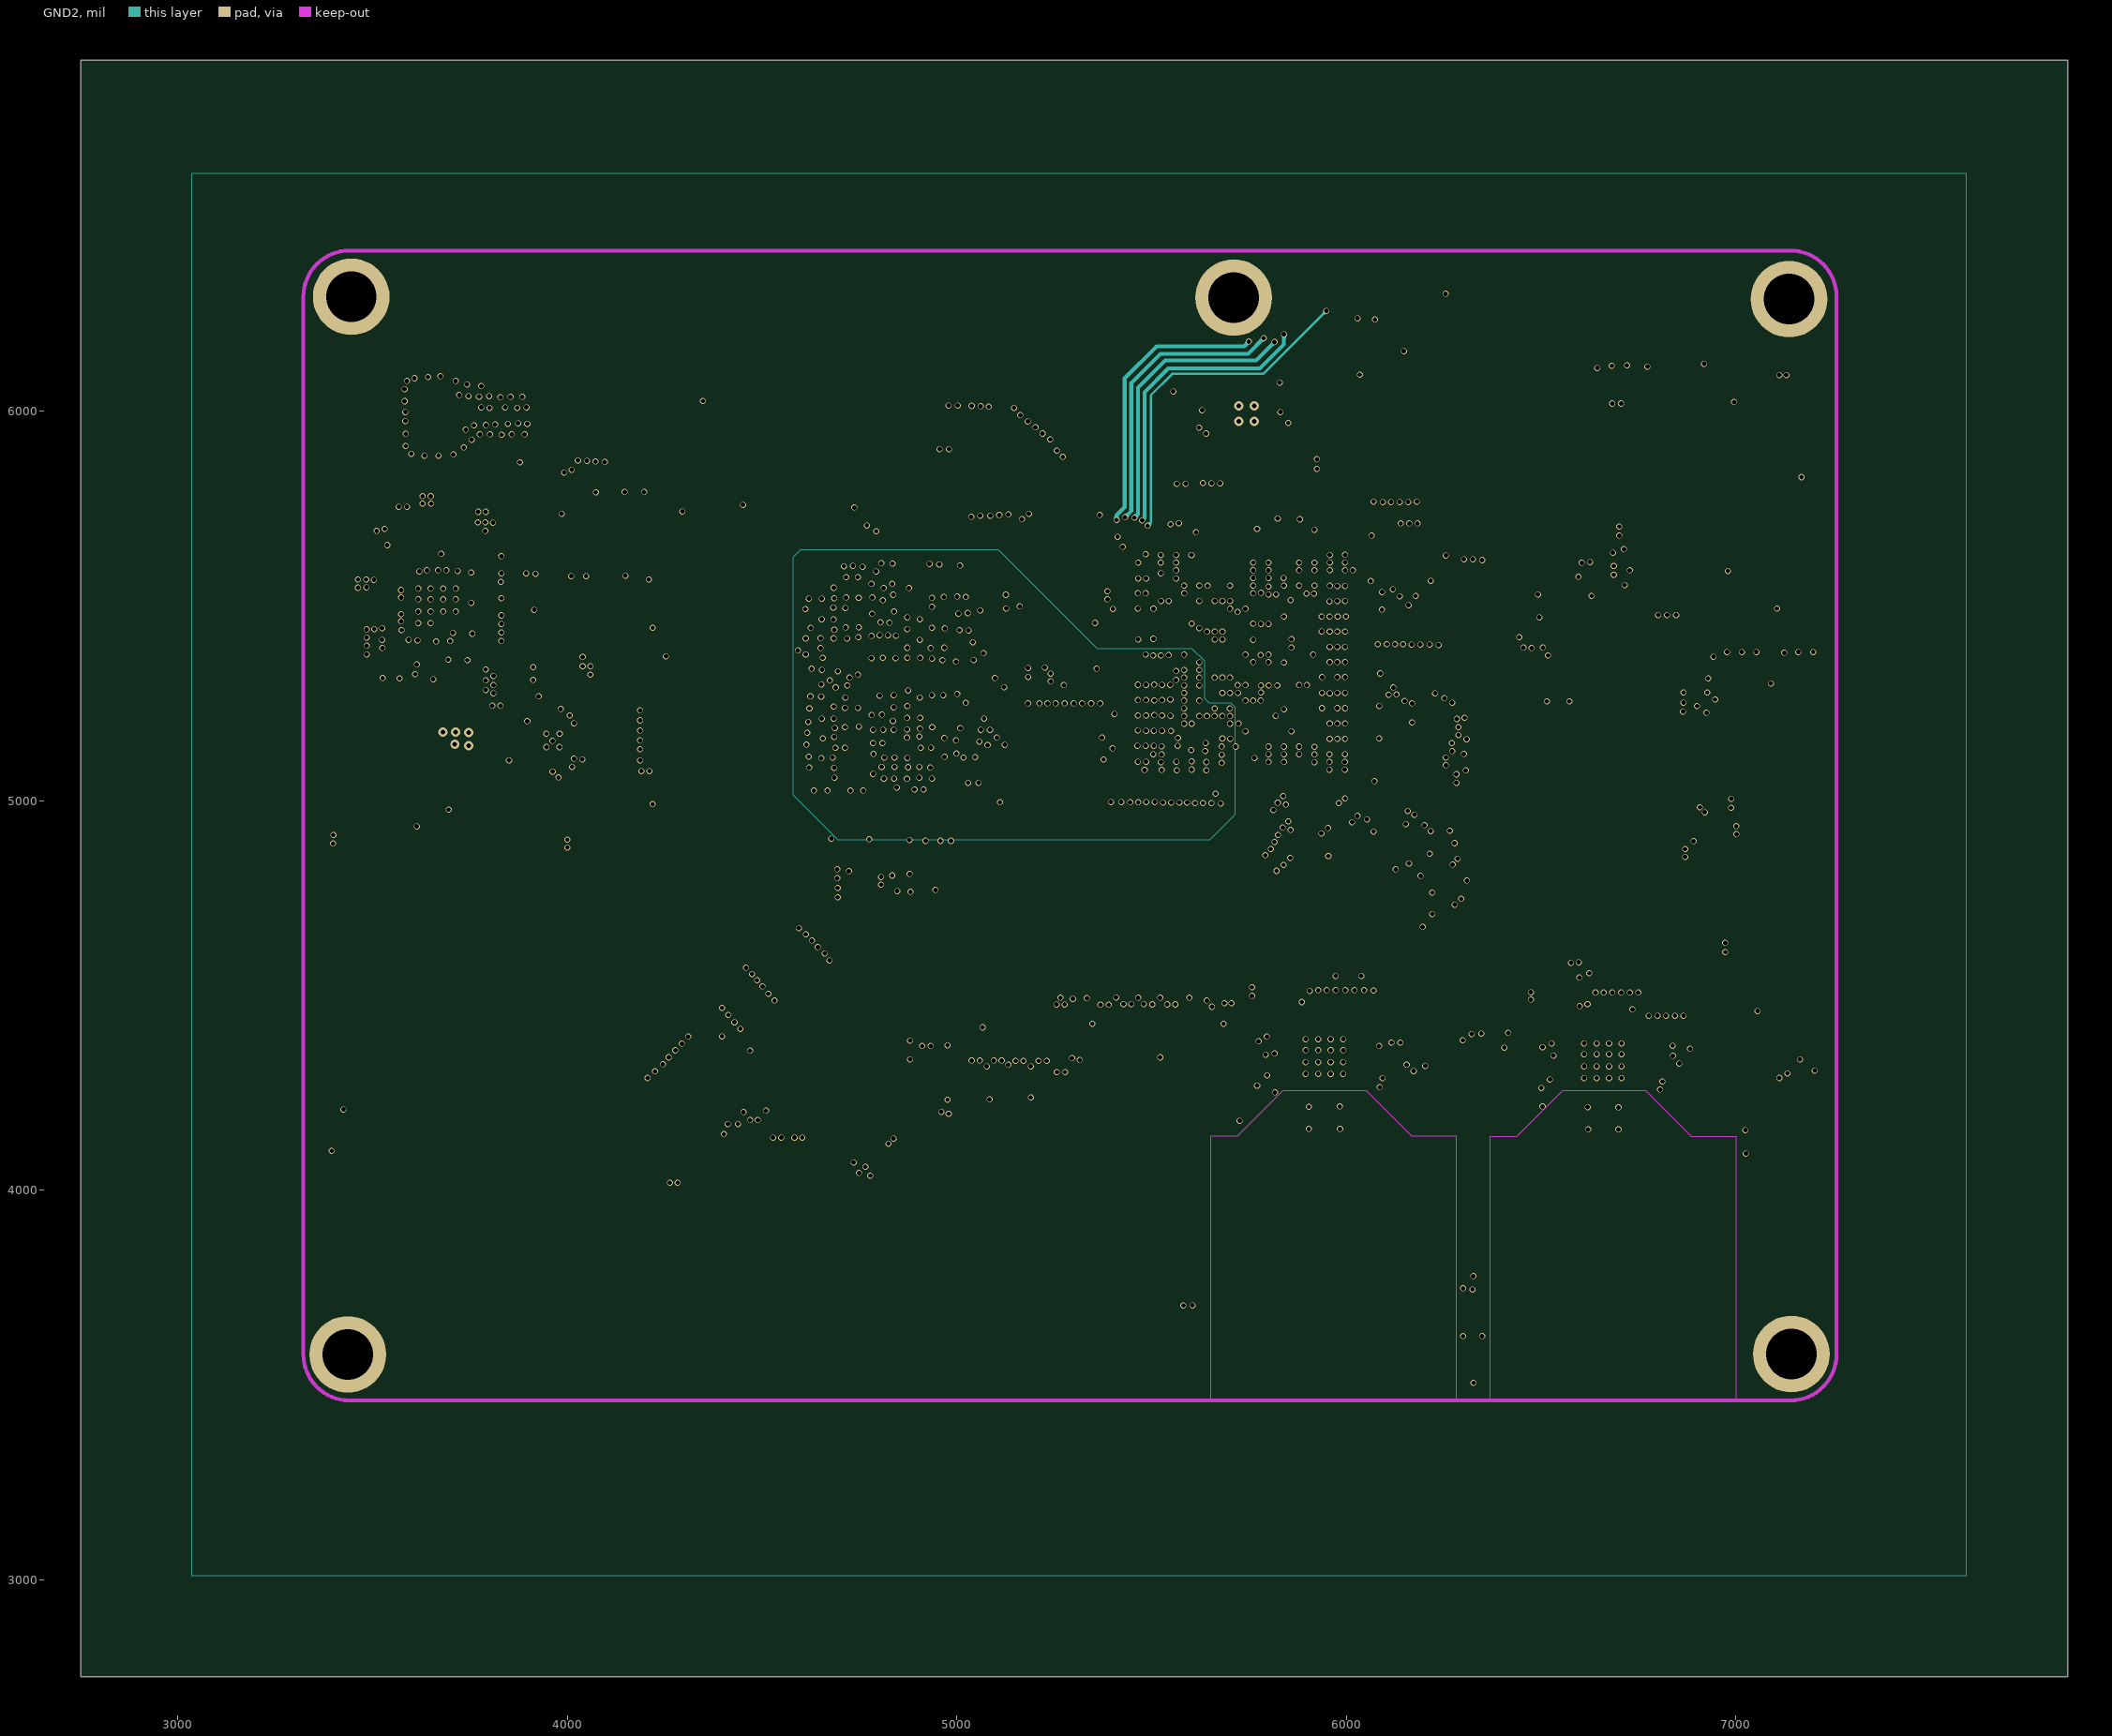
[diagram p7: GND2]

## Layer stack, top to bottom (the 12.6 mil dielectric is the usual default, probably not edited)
Top Layer: signal copper (thickness not stored)
Dielectric: dielectric 12.6, FR-4, Dk 4.8
GND1: signal copper (thickness not stored)
Dielectric: dielectric 12.6, FR-4, Dk 4.8
内层2: signal copper (thickness not stored)
Dielectric: dielectric 12.6, FR-4, Dk 4.8
VCC: signal copper (thickness not stored)
Dielectric: dielectric 12.6, FR-4, Dk 4.8
内层4: signal copper (thickness not stored)
Dielectric: dielectric 12.6, FR-4, Dk 4.8
Inner5: signal copper (thickness not stored)
Dielectric: dielectric 12.6, FR-4, Dk 4.8
GND2: signal copper (thickness not stored)
Dielectric: dielectric 12.6, FR-4, Dk 4.8
Bottom Layer: signal copper (thickness not stored)

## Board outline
7852.8,2750 2750,2750 2750,6902 7852.8,6902

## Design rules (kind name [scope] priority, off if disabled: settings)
Clearance safeClearance [All] p1: gap=7 ignorepadtopadclearanceinfootprint=FALSE except(3.5: Track-Track Track-SMDPad SMDPad-SMDPad Track-THPad SMDPad-THPad THPad-THPad Track-Via SMDPad-Via THPad-Via Via-Via Track-Fill SMDPad-Fill THPad-Fill Via-Fill Fill-Fill Track-Region SMDPad-Region THPad-Region Via-Region Fill-Region Region-Region Track-Poly SMDPad-Poly THPad-Poly Via-Poly Fill-Poly Region-Poly Poly-Poly Track-Text SMDPad-Text THPad-Text Via-Text Fill-Text Region-Text Poly-Text Text-Text SMDPad-Sheet THPad-Sheet Track-Hole SMDPad-Hole THPad-Hole Via-Hole Fill-Hole Region-Hole Poly-Hole Text-Hole Sheet-Hole; 11.8: Track-Sheet Via-Sheet Fill-Sheet Region-Sheet Poly-Sheet Text-Sheet)
DiffPairsRouting differentialPair [All] p1: maxuncoupledlength=50 minlimit=0 maxlimit=4 mostfreqgap=4 toplayer_minwidth=3 toplayer_prefwidth=10 toplayer_maxwidth=100 bottomlayer_minwidth=3 bottomlayer_prefwidth=10 bottomlayer_maxwidth=100 midlayer1_minwidth=3 midlayer1_prefwidth=10 midlayer1_maxwidth=100 midlayer2_minwidth=3 midlayer2_prefwidth=10 midlayer2_maxwidth=100 midlayer3_minwidth=3 midlayer3_prefwidth=10 midlayer3_maxwidth=100 midlayer4_minwidth=3 midlayer4_prefwidth=10 midlayer4_maxwidth=100 midlayer5_minwidth=3 midlayer5_prefwidth=10 midlayer5_maxwidth=100 midlayer6_minwidth=3 midlayer6_prefwidth=10 midlayer6_maxwidth=100
PasteMaskExpansion pasteMaskExpansion [All] p1: expansion=0
PlaneConnect innerPlane [All] p1: planeconnectstyle=Relief reliefexpansion=20 reliefentries=4 reliefconductorwidth=10 reliefairgap=10
PolygonConnect copperRegion [All] p1: connectstyle=Relief reliefentries=4 reliefconductorwidth=10 polygonreliefangle="90 Angle" airgapwidth=10
PolygonConnect TBCopper [All] p1: connectstyle=Relief reliefentries=4 reliefconductorwidth=6 polygonreliefangle="90 Angle" airgapwidth=6
PolygonConnect DRAMCopper [All] p1: connectstyle=Relief reliefentries=4 reliefconductorwidth=4 polygonreliefangle="90 Angle" airgapwidth=4
RoutingVias viaSize [All] p1: viastyle="Through Hole" holewidth=7.9 minholewidth=7.9 maxholewidth=236.2 width=17.7 minwidth=15.7 maxwidth=393.7
SolderMaskExpansion solderMaskExpansion [All] p1: useseparateexpansions=TRUE expansion=4 expansionbottom=4
Width trackWidth [All] p1: maxlimit=100 minlimit=3 preferedwidth=4

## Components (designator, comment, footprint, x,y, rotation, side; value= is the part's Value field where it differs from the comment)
C13 "0201X225M6R3NT" "c0201 nsk" 5535.45,5450.18 r270 bottom
C14 "0201X225M6R3NT" "c0201 nsk" 5556.49,5450.35 r270 bottom
C19 "0201X225M6R3NT" "c0201 nsk" 5737.8,5320 r90 bottom
C20 "0201X225M6R3NT" "c0201 nsk" 5721.8,5245 r270 bottom
C21 "0201X225M6R3NT" "c0201 nsk" 5782.8,5225 r270 bottom
C22 "0201X225M6R3NT" "c0201 nsk" 5760.8,5225 r270 bottom
C23 "0201X225M6R3NT" "c0201 nsk" 5740.8,5225 r270 bottom
C24 "0201X225M6R3NT" "c0201 nsk" 5759.8,5320 r90 bottom
C26 "GRM155R60J226ME11D" c0402-nsk 3577.8,5598 r90 bottom
C29 "GRM155R60J226ME11D" c0402-nsk 3529.81,5504.72 r180 bottom
C30 "GRM033R61A105ME44D" "c0201 nsk" 3734.8,5406 r0 bottom
C32 "GRM155R60J226ME11D" c0402-nsk 3523.8,5599 r90 bottom
C34 "GRM155R60J226ME11D" c0402-nsk 3482.8,5600 r90 bottom
C36 "0201X225M6R3NT" "c0201 nsk" 5679.55,5350.75 r90 bottom
C37 "0201X225M6R3NT" "c0201 nsk" 5660.55,5350.75 r90 bottom
C38 "0201X225M6R3NT" "c0201 nsk" 5699.34,5350.11 r90 bottom
C39 "0201X225M6R3NT" "c0201 nsk" 5718.91,5349.97 r90 bottom
C40 "0201X225M6R3NT" "c0201 nsk" 5640.8,5351 r90 bottom
C41 "0201X225M6R3NT" "c0201 nsk" 5678.8,5297 r180 bottom
C42 "GRM155R60J226ME11D" c0402-nsk 3470.8,5525 r270 bottom
C46 "0201X225M6R3NT" "c0201 nsk" 3734.8,5429 r180 bottom
C47 "0201X225M6R3NT" "c0201 nsk" 5767.8,5392 r180 bottom
C48 "0201X225M6R3NT" "c0201 nsk" 5800.8,5266 r270 bottom
C49 "0201X225M6R3NT" "c0201 nsk" 5800.8,5321 r90 bottom
C50 "0201X225M6R3NT" "c0201 nsk" 5780.8,5321 r90 bottom
C56 "CL05A225KP5NSNC" c0402-nsk 3737.8,5560 r0 bottom
C57 "0201X225M6R3NT" "c0201 nsk" 5922.8,5391 r0 bottom
C58 "0201X225M6R3NT" "c0201 nsk" 5922.8,5369 r0 bottom
C67 "0201X225M6R3NT" "c0201 nsk" 5922.8,5413 r0 bottom
C68 "0201X225M6R3NT" "c0201 nsk" 5899.8,5433 r180 bottom
C75 "0201X225M6R3NT" "c0201 nsk" 5818.55,5484.75 r90 bottom
C76 "0201X225M6R3NT" "c0201 nsk" 5799.55,5484.75 r90 bottom
C77 "0201X225M6R3NT" "c0201 nsk" 5761.55,5484.75 r90 bottom
C78 "0201X225M6R3NT" "c0201 nsk" 5780.55,5484.75 r90 bottom
C79 "CL05A475KP5NRNC" c0402-nsk 3529.8,5470 r0 bottom
C82 "CL05A475KP5NRNC" c0402-nsk 3737.8,5527 r0 bottom
C83 "0201X225M6R3NT" "c0201 nsk" 5660.03,5395.81 r270 bottom
C84 "0201X225M6R3NT" "c0201 nsk" 5641.03,5395.81 r270 bottom
C85 "0201X225M6R3NT" "c0201 nsk" 5678.8,5395.64 r270 bottom
C86 "0201X225M6R3NT" "c0201 nsk" 5699.03,5395.81 r270 bottom
C90 "GRM033R61A104KE15D" "c0201 nsk" 5546.8,5418 r180 bottom
C91 "GRM033R61A104KE15D" "c0201 nsk" 5788.8,5172 r270 bottom
C92 "GRM033R61A104KE15D" "c0201 nsk" 5525.8,5491 r270 bottom
C93 "GRM033R61A104KE15D" "c0201 nsk" 5546.8,5397 r180 bottom
C94 "GRM033R61A104KE15D" "c0201 nsk" 5431.8,5494 r180 bottom
C102 "GRM033R61A104KE15D" "c0201 nsk" 5598.8,5513 r0 bottom
C103 "GRM033R61A104KE15D" "c0201 nsk" 5593.8,5568 r180 bottom
C104 "GRM033R61A104KE15D" "c0201 nsk" 5850.8,5452 r180 bottom
C105 "GRM033R61A104KE15D" "c0201 nsk" 5523.8,5670 r270 bottom
C106 "GRM033R61A104KE15D" "c0201 nsk" 5689.8,5653 r270 bottom
C107 "GRM033R61A104KE15D" "c0201 nsk" 5746.8,5664 r180 bottom
C108 "GRM033R61A104KE15D" "c0201 nsk" 5661.8,5583 r0 bottom
C109 "GRM033R61A104KE15D" "c0201 nsk" 5593.55,5589.25 r180 bottom
C110 "GRM033R61A104KE15D" "c0201 nsk" 5593.55,5611.25 r180 bottom
C111 "GRM033R61A104KE15D" "c0201 nsk" 5625.8,5600 r270 bottom
C112 "GRM033R61A104KE15D" "c0201 nsk" 5682.8,5533 r180 bottom
C113 "GRM033R61A104KE15D" "c0201 nsk" 5632.8,5533 r0 bottom
C114 "GRM033R61A104KE15D" "c0201 nsk" 5661.8,5560 r0 bottom
C115 "GRM033R61A104KE15D" "c0201 nsk" 5502.8,5669.5 r270 bottom
C116 "0201X225M6R3NT" "c0201 nsk" 4642.8,5062 r180 bottom
C117 "0201X225M6R3NT" "c0201 nsk" 4666.8,5190 r90 bottom
C118 "GRM033R61A104KE15D" "c0201 nsk" 4900.8,5110 r180 bottom
C119 "GRM033R61A104KE15D" "c0201 nsk" 5641.8,5191 r90 bottom
C120 "GRM033R61A104KE15D" "c0201 nsk" 4816.8,5403 r180 bottom
C121 "GRM033R61A104KE15D" "c0201 nsk" 4920.3,5347 r0 bottom
C122 "GRM033R61A104KE15D" "c0201 nsk" 5037.8,5201 r0 bottom
C123 "GRM033R61A104KE15D" "c0201 nsk" 5023.8,5151 r270 bottom
C124 "GRM033R61A104KE15D" "c0201 nsk" 4753.8,5116 r0 bottom
C125 "GRM033R61A104KE15D" "c0201 nsk" 4943.8,5597 r0 bottom
C126 "GRM033R61A104KE15D" "c0201 nsk" 5595.3,5252 r0 bottom
C127 "GRM033R61A104KE15D" "c0201 nsk" 5594.8,5275 r0 bottom
C128 "GRM033R61A104KE15D" "c0201 nsk" 5594.8,5336 r0 bottom
C129 "GRM033R61A104KE15D" "c0201 nsk" 5681.8,5192 r90 bottom
C130 "GRM033R61A104KE15D" "c0201 nsk" 4731.8,5467 r180 bottom
C132 "0201X225M6R3NT" "c0201 nsk" 5389.8,5196 r270 bottom
C133 "GRM033R61A104KE15D" "c0201 nsk" 5602.8,5168 r90 bottom
C134 "0201X225M6R3NT" "c0201 nsk" 4890.8,5240 r90 bottom
C135 "GRM033R61A104KE15D" "c0201 nsk" 4836.8,5162 r0 bottom
C137 "GRM033R61A104KE15D" "c0201 nsk" 4727.8,5208 r0 bottom
C138 "GRM033R61A104KE15D" "c0201 nsk" 4978.8,5186 r180 bottom
C141 "GRM033R61A104KE15D" "c0201 nsk" 4890.8,5435 r225 bottom
C142 "0201X225M6R3NT" "c0201 nsk" 4740.8,5290 r270 bottom
C143 "0201X225M6R3NT" "c0201 nsk" 4688.8,5586 r90 bottom
C144 "GRM033R61A104KE15D" "c0201 nsk" 4866.8,5596 r180 bottom
C145 "GRM033R61A104KE15D" "c0201 nsk" 5009.8,5502 r0 bottom
C151 "GRM033R61A104KE15D" "c0201 nsk" 4806.8,5200 r180 bottom
C152 "GRM033R61A104KE15D" "c0201 nsk" 4906.8,5007 r180 bottom
C153 "GRM033R61A104KE15D" "c0201 nsk" 5594.8,5296 r0 bottom
C154 "GRM033R61A104KE15D" "c0201 nsk" 5594.8,5316 r0 bottom
C155 "GRM033R61A104KE15D" "c0201 nsk" 5621.8,5191 r90 bottom
C156 "GRM033R61A104KE15D" "c0201 nsk" 4675.8,5351 r0 bottom
C161 "0201X225M6R3NT" "c0201 nsk" 5370.8,5196 r270 bottom
C162 "GRM033R61A104KE15D" "c0201 nsk" 5351.8,5196 r90 bottom
C163 "GRM033R61A104KE15D" "c0201 nsk" 5752.8,5158 r180 bottom
C164 "GRM033R61A104KE15D" "c0201 nsk" 5752.8,5179 r180 bottom
C165 "GRM033R61A104KE15D" "c0201 nsk" 5819.8,5564 r270 bottom
C166 "GRM033R61A104KE15D" "c0201 nsk" 5814.8,5187 r90 bottom
C167 "GRM033R61A104KE15D" "c0201 nsk" 5885.8,5328 r225 bottom
C168 "GRM033R61A104KE15D" "c0201 nsk" 5900.8,5314 r225 bottom
C169 "GRM033R61A104KE15D" "c0201 nsk" 5869.8,5161 r180 bottom
C170 "GRM033R61A104KE15D" "c0201 nsk" 5858.8,5557 r270 bottom
C171 "GRM033R61A104KE15D" "c0201 nsk" 5836.8,5187 r90 bottom
C172 "GRM033R61A104KE15D" "c0201 nsk" 5543.8,5615 r270 bottom
C173 "GRM033R61A104KE15D" "c0201 nsk" 5829.8,5395 r0 bottom
C174 "GRM033R61A104KE15D" "c0201 nsk" 5829.8,5375 r0 bottom
C175 "GRM033R61A104KE15D" "c0201 nsk" 5877.8,5265 r90 bottom
C176 "GRM033R61A104KE15D" "c0201 nsk" 5898.8,5265 r90 bottom
C177 "GRM033R61A104KE15D" "c0201 nsk" 5603.8,5386 r270 bottom
C178 "GRM033R61A104KE15D" "c0201 nsk" 5581.18,5385.75 r270 bottom
C181 "GRM033R61A104KE15D" "c0201 nsk" 5417.16,5622.04 r225 bottom
C182 "GRM033R61A104KE15D" "c0201 nsk" 5430.59,5608.61 r225 bottom
C183 "GRM033R61A104KE15D" "c0201 nsk" 5328.08,5758.12 r180 bottom
C184 "GRM033R61A104KE15D" "c0201 nsk" 5327.77,5778.12 r180 bottom
C185 "GRM033R61A104KE15D" "c0201 nsk" 5845.8,5253 r180 bottom
C186 "GRM033R61A104KE15D" "c0201 nsk" 5845.8,5272 r180 bottom
C187 "GRM033R61A104KE15D" "c0201 nsk" 5832.8,5332 r0 bottom
C188 "GRM033R61A104KE15D" "c0201 nsk" 5850.8,5473 r180 bottom
C200 "CAP_0402" c0402-nsk 6902.81,5348.72 r180 bottom
C201 "GRM033R61A104KE15D" "c0201 nsk" 5868.8,5233 r180 bottom
C202 "GRM033R61A104KE15D" "c0201 nsk" 5503.8,5605 r315 bottom
C204 "GRM033R61A104KE15D" "c0201 nsk" 7212.8,4115.5 r90 bottom
C208 "GRM033R61A104KE15D" "c0201 nsk" 5738.8,5423 r90 bottom
C209 "GRM033R61A104KE15D" "c0201 nsk" 5798.8,5422 r90 bottom
C211 "GRM033R61A104KE15D" "c0201 nsk" 5900.8,5492 r0 bottom
C213 "GRM033R61A104KE15D" "c0201 nsk" 5900.8,5513 r0 bottom
C214 "GRM033R61A104KE15D" "c0201 nsk" 5933.8,5525 r270 bottom
C215 "GRM033R61A104KE15D" "c0201 nsk" 5900.3,5452 r0 bottom
C216 "GRM033R61A104KE15D" "c0201 nsk" 5900.3,5472 r0 bottom
C223 "CAP_0402" c0402-nsk 5415.92,4342.11 r270 bottom
C224 "CAP_0402" c0402-nsk 5384.9,4342.17 r270 bottom
C225 "0201X225M6R3NT" "c0201 nsk" 4957.8,4736 r0 bottom
C226 "GRM033R61A104KE15D" "c0201 nsk" 4957.8,4755 r180 bottom
C227 "GRM033R61A104KE15D" "c0201 nsk" 5752.8,5137 r180 bottom
C228 "0201X225M6R3NT" "c0201 nsk" 7101.8,5318 r0 bottom
C229 "GRM033R61A104KE15D" "c0201 nsk" 4901.55,4761.25 r270 bottom
C230 "GRM033R61A104KE15D" "c0201 nsk" 4861.8,4749 r0 bottom
C231 "0201X225M6R3NT" "c0201 nsk" 5017.3,4929 r0 bottom
C232 "GRM033R61A104KE15D" "c0201 nsk" 5016.8,4906 r180 bottom
C233 "GRM033R61A104KE15D" "c0201 nsk" 5016.8,4884 r180 bottom
C234 "0201X225M6R3NT" "c0201 nsk" 7101.8,5341 r0 bottom
C235 "GRM033R61A104KE15D" "c0201 nsk" 4920.55,4761.25 r270 bottom
C236 "GRM033R61A104KE15D" "c0201 nsk" 7101.8,5292 r180 bottom
C237 "CAP_0402" c0402-nsk 6124.57,6134.49 r90 bottom
C238 "GRM033R61A104KE15D" "c0201 nsk" 6096.57,6148.49 r90 bottom
C239 "GRM033R61A104KE15D" "c0201 nsk" 6096.57,6231.49 r270 bottom
C240 "GRM033R61A104KE15D" "c0201 nsk" 6118.57,6231.49 r270 bottom
C241 "GRM033R61A104KE15D" "c0201 nsk" 6073.57,6148.49 r90 bottom
C242 "CAP_0402" c0402-nsk 5984.53,6163.85 r180 bottom
C243 "CAP_0402" c0402-nsk 5984.8,6198 r180 bottom
C246 "CAP_0402" c0402-nsk 7138.79,4455.28 r0 bottom
C247 "CAP_0402" c0402-nsk 3632.8,4955 r180 bottom
C248 "CAP_1206" C1206 5626.8,4033 r90 bottom
C255 "CAP_1206" C1206 6336.8,4031 r90 bottom
C276 "0201X225M6R3NT" "c0201 nsk" 6854.8,5438 r270 bottom
C277 "0201X225M6R3NT" "c0201 nsk" 6841.8,5295 r270 bottom
C285 "CL10A226MP8NUNE" C0603-NSK 3698.8,5676 r270 bottom
C286 "CL10A226MP8NUNE" C0603-NSK 3651.8,5676 r270 bottom
C287 "CL10A226MP8NUNE" C0603-NSK 3725.8,5477 r0 bottom
C288 "CL10A226MP8NUNE" C0603-NSK 3736.8,5329.54 r0 bottom
C289 "CL10A226MP8NUNE" C0603-NSK 3736.8,5279.54 r0 bottom
C294 "CAP_1206" C1206 4752.8,4119 r270 bottom
D16 "0402ESDA-05N" D0402 6923.8,5441 r270 bottom
D17 "0402ESDA-05N" D0402 6959.8,5442 r90 bottom
D18 "0402ESDA-05N" D0402 6997.04,5442.16 r270 bottom
D19 "0402ESDA-05N" D0402 7034.8,5442 r90 bottom
D20 "0402ESDA-05N" D0402 7070.8,5442 r270 bottom
D21 "0402ESDA-05N" D0402 7106.8,5442 r90 bottom
D22 "0402ESDA-05N" D0402 7143.8,5442 r270 bottom
D23 "0402ESDA-05N" D0402 7178.8,5442 r90 bottom
FPC1 "FPC-05FB-50PH20" FPC-SMD_50P-P0.50_FPC-05FB-50PH20 3474.8,4465 r90 bottom
FPC2 "FPC-05FB-30PH20" FPC-SMD_30P-P0.50_FPC-05FB-30PH20 7109.8,4866 r270 bottom
IMPORTED_IMAGE "IMPORTED_IMAGE" IMPORTED_IMAGE 4855.8,6160 r0 top
IMPORTED_IMAGE "IMPORTED_IMAGE" IMPORTED_IMAGE 6903.8,4861 r0 top
R24 "Res_0201" "r0201 nsk" 5668.8,5491 r0 bottom
R26 "Res_0201" "r0201 nsk" 5711.8,5653 r270 bottom
R27 "Res_0201" "r0201 nsk" 5743.8,5644 r180 bottom
R28 "Res_0402" R0402-NSK 5670.8,5610 r180 bottom
R38 "Res_0201" "r0201 nsk" 5660.8,5146 r90 bottom
R39 "Res_0201" "r0201 nsk" 4867.8,5021 r90 bottom
R40 "Res_0201" "r0201 nsk" 4755.8,5062 r90 bottom
R44 "Res_0201" "r0201 nsk" 5946.8,5258.47 r180 bottom
R45 "Res_0201" "r0201 nsk" 6045.8,5324 r0 bottom
R46 "Res_0201" "r0201 nsk" 5946.8,5218 r180 bottom
R49 "Res_0201" "r0201 nsk" 6046.8,5286 r180 bottom
R55 "Res_0201" "r0201 nsk" 5927.8,5171.53 r0 bottom
R56 "Res_0201" "r0201 nsk" 5327.8,4021.53 r0 bottom
R57 "Res_0201" "r0201 nsk" 5327.8,4043.53 r0 bottom
R59 "Res_0201" "r0201 nsk" 5927.8,5197 r0 bottom
R63 "Res_0201" "r0201 nsk" 6892.8,5451 r90 bottom
R64 "Res_0201" "r0201 nsk" 6118.57,6189.49 r270 bottom
R65 "Res_0201" "r0201 nsk" 6096.57,6189.49 r90 bottom
R66 "Res_0201" "r0201 nsk" 6073.57,6190.49 r90 bottom
R67 "Res_0201" "r0201 nsk" 5969.8,6138 r180 bottom
R68 "Res_0201" "r0201 nsk" 5969.8,6225 r180 bottom
R73 "Res_0201" "r0201 nsk" 5893.8,6135 r0 bottom
R74 "Res_0201" "r0201 nsk" 5950.8,5980 r90 bottom
R75 "Res_0201" "r0201 nsk" 5542.8,6029 r90 bottom
R76 "Res_0201" "r0201 nsk" 7030.8,4198 r270 bottom
R115 "Res_0201" "r0201 nsk" 6760.8,5282 r90 bottom
R116 "Res_0201" "r0201 nsk" 6738.8,5282 r270 bottom
R119 "Res_0201" "r0201 nsk" 6748.8,5483 r180 bottom
R122 "Res_0201" "r0201 nsk" 6048.57,6190.49 r90 bottom
R126 "Res_0402" R0402-NSK 6814.8,5268 r90 bottom
R127 "Res_0201" "r0201 nsk" 6031.8,5562 r180 bottom
R128 "Res_0201" "r0201 nsk" 6031.8,5539 r180 bottom
SIM1 "1040310811" SIM-SMD_8P-1040310811 7001.8,5769 r270 bottom
U11 "TJA1051T_C7432801" SOP-8_L4.9-W3.9-P1.27-LS6.0-BL 7137.8,4287 r0 bottom
U16 "SY6280AAC_C55136" SOT-23-5_L3.0-W1.7-P0.95-LS2.8-BL 6777.31,5385.73 r180 bottom
U18 "W25N01GVZEIG_C88868" WSON-8_L8.0-W6.10-P1.27-BL-EP 5743.8,5994 r270 bottom

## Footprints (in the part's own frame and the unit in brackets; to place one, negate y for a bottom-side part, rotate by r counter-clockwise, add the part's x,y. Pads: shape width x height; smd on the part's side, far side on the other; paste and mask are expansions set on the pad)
"c0201 nsk" [mil]
  rect 14.51x12.76 smd: 1(-11.5,0) 2(11,0)
c0402-nsk [mil]
  rect 22x22 smd: 1(-19.99,0) 2(20.01,0)
  silkscreen extent 0,-5 0,6
C0603-NSK [mm]
  rect 0.85x0.85 smd: 1(-0.75,0) 2(0.75,0)
  silkscreen extent 0,-0.21 0,0.21
C1206 [mm]
  rect 1.485x1.728 smd: 1(-1.593,0) 2(1.593,0)
  silkscreen extent -2.56,-1.09 2.56,1.09
D0402 [mil]
  rect 19.89x21.68 smd: 1(-16.4,0) 2(16.4,0)
  silkscreen extent -37,-9 -31,9
FPC-SMD_30P-P0.50_FPC-05FB-30PH20 [mm]
  rect 0.3x1.2 smd: 1(7.25,1.625) 2(6.75,1.625) 3(6.25,1.625) 4(5.75,1.625) 5(5.25,1.625) 6(4.75,1.625) 7(4.25,1.625) 8(3.75,1.625) 9(3.25,1.625) 10(2.75,1.625) 11(2.25,1.625) 12(1.75,1.625) 13(1.25,1.625) 14(0.75,1.625) 15(0.25,1.625) 16(-0.25,1.625) 17(-0.75,1.625) 18(-1.25,1.625) 19(-1.75,1.625) 20(-2.25,1.625) 21(-2.75,1.625) 22(-3.25,1.625) 23(-3.75,1.625) 24(-4.25,1.625) 25(-4.75,1.625) 26(-5.25,1.625) 27(-5.75,1.625) 28(-6.25,1.625) 29(-6.75,1.625) 30(-7.25,1.625)
  rect 2x1.8 smd: 31(-8.8,-1.625) 32(8.8,-1.625)
  silkscreen extent -9.25,-3.55 9.25,2.13
FPC-SMD_50P-P0.50_FPC-05FB-50PH20 [mm]
  rect 0.3x1.2 smd: 1(12.25,1.625) 2(11.75,1.625) 3(11.25,1.625) 4(10.75,1.625) 5(10.25,1.625) 6(9.75,1.625) 7(9.25,1.625) 8(8.75,1.625) 9(8.25,1.625) 10(7.75,1.625) 11(7.25,1.625) 12(6.75,1.625) 13(6.25,1.625) 14(5.75,1.625) 15(5.25,1.625) 16(4.75,1.625) 17(4.25,1.625) 18(3.75,1.625) 19(3.25,1.625) 20(2.75,1.625) 21(2.25,1.625) 22(1.75,1.625) 23(1.25,1.625) 24(0.75,1.625) 25(0.25,1.625) 26(-0.25,1.625) 27(-0.75,1.625) 28(-1.25,1.625) 29(-1.75,1.625) 30(-2.25,1.625) 31(-2.75,1.625) 32(-3.25,1.625) 33(-3.75,1.625) 34(-4.25,1.625) 35(-4.75,1.625) 36(-5.25,1.625) 37(-5.75,1.625) 38(-6.25,1.625) 39(-6.75,1.625) 40(-7.25,1.625) 41(-7.75,1.625) 42(-8.25,1.625) 43(-8.75,1.625) 44(-9.25,1.625) 45(-9.75,1.625) 46(-10.25,1.625) 47(-10.75,1.625) 48(-11.25,1.625) 49(-11.75,1.625) 50(-12.25,1.625)
  rect 2x1.8 smd: 51(-13.8,-1.625) 52(13.8,-1.625)
  silkscreen extent -14.25,-3.88 14.25,2.13
IMPORTED_IMAGE [mil]
"r0201 nsk" [mil]
  rect 11.93x12.76 smd: 1(-9.51,0) 2(9.51,0)
R0402-NSK [mil]
  rect 19.68x22 smd: 1(-18,0) 2(18,0)
SIM-SMD_8P-1040310811 [mm]
  rect 0.7x1.2 smd: 1(3.138,-5.337) 2(2.037,-5.337) 3(0.938,-5.337) 4(-0.162,-5.337) 5(-1.263,-5.337) 6(-2.363,-5.337) 7(-3.462,-5.337) 8(-4.562,-5.337)
  rect 1.17x1.8 smd: 9(-5.773,-5.138)
  rect 1.55x1.35 smd: 10(5.598,-5.313)
  rect 1.2x1 smd: 11(5.773,0.663) 12(5.773,4.363)
  rect 1.9x1.35 smd: 13(2.273,5.337) 14(-3.697,5.337)
  silkscreen extent -6.07,-5.64 5.99,5.67
SOP-8_L4.9-W3.9-P1.27-LS6.0-BL [mm]
  oval 0.63x1.865 smd: 1(-1.905,-2.682) 2(-0.635,-2.682) 3(0.635,-2.682) 4(1.905,-2.682) 5(1.905,2.682) 6(0.635,2.682) 7(-0.635,2.682) 8(-1.905,2.682)
  silkscreen extent -2.82,-2.83 2.58,1.52
SOT-23-5_L3.0-W1.7-P0.95-LS2.8-BL [mm]
  rect 0.49x1.157 smd: 1(-0.95,-1.154) 2(0,-1.154) 3(0.95,-1.154)
  rect 0.49x1.175 smd: 4(0.95,1.154) 5(-0.95,1.154)
  silkscreen extent -1.8,-1.29 1.53,0.85
WSON-8_L8.0-W6.10-P1.27-BL-EP [mm]
  oval 0.56x1.4 smd: 1(-1.905,-4.027) 2(-0.635,-4.027) 3(0.635,-4.027) 4(1.905,-4.027) 5(1.905,4.027) 6(0.635,4.027) 7(-0.635,4.027) 8(-1.905,4.027)
  rect 4.3x3.4 smd: 9(0,0)
  silkscreen extent -3.08,-4.98 3.08,4.08

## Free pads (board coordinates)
  round 196.85 hole 129.92: 54(3435.8,3578) 54(3444.8,6294) 54(5710.8,6292) 54(7136.8,6288) 54(7142.8,3579)

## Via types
v1: diameter 15.75, hole 11.8, Top Layer to Bottom Layer, 496 vias
v2: diameter 15.7, hole 11.8, Top Layer to Bottom Layer, 335 vias
v3: diameter 15.75, hole 11.81, Top Layer to Bottom Layer, 279 vias
v4: diameter 24, hole 12, Top Layer to Bottom Layer, 9 vias

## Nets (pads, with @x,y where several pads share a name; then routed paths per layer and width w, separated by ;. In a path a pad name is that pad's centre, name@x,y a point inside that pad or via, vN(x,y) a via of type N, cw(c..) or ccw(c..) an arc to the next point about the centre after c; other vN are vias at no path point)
323-DCDC1/2: C19.1 C20.1 C21.1 C22.1 C23.1 C24.1 | length 271
  Bottom Layer w10: C20.1@5719.3,5257 5721.8,5259.5 v2(5721.8,5277) 5721.8,5296 v2(5720.8,5297) v2(5740.8,5297) ; C23.1@5740.8,5236.5 v2(5740.78,5257.04) ; C21.1@5782.8,5237 5782.3,5236.5 C22.1@5760.8,5236.5 5760.8,5256.71 v2(5760.47,5257.04) ; v2(5740.78,5257.04) v2(5740.8,5297) ; v2(5740.78,5257.04) v2(5760.47,5257.04) ; v2(5740.8,5297) 5740.8,5305.5 C19.1@5737.8,5308.5 C24.1@5759.8,5308.5 5760.47,5307.83 v2(5760.47,5257.04)
  other v1: 4189.8,5076 4210.39,5076 4186.8,5104 4186.8,5132.37 4186.8,5154.8 4186.8,5180.01 4186.8,5206.33 4186.8,5232.09
323-DCDC3: C83.1 C84.1 C85.1 C86.1 | length 119.7
  Bottom Layer w10: C84.1@5641.03,5407.31 C83.1@5660.03,5407.31 ; v2(5662.04,5434.21) v2(5662.04,5414.21) 5662.04,5409.32 C83.1@5660.03,5407.31 ; C85.1@5678.8,5407.14 5681.73,5410.07 v2(5681.73,5434.21) ; C86.1@5699.03,5407.31 5688.63,5407.31 v2(5681.73,5414.21) 5674.82,5407.31 C83.1@5660.03,5407.31
  other v1: 4058.75,5323.63 4038.8,5345.34 4059.18,5345.34 4038.8,5369
$3N7591: R38.1 | length 33
  Bottom Layer w6: R38.1@5659.72,5135.46 5660.72,5134.46 5660.72,5124.97 5667.43,5118.26 v3(5680.01,5118.26)
$3N7643: R39.1 | length 36.5
  Bottom Layer w4.5: v3(4845.72,5033.97) 4845.72,5023.97 4856.56,5013.13 R39.1@4867.72,5013.13
$3N7644: R40.1 | length 28
  Bottom Layer w4.5: R40.1@4756.01,5052.45 4756.01,5029.6 v3(4759.64,5025.97)
$6N1044: R44.2 | length 18.7
  Bottom Layer w6: R44.2@5937.29,5258.47 5937.63,5258.8 v1(5937.63,5277.04)
$6N1104: R46.2 | length 19.8
  Bottom Layer w6: R46.2@5937.29,5218 5937.29,5237.33 v1(5937.63,5237.67)
$6N1424: R55.2 | length 25.2
  Bottom Layer w10: R55.2@5937.31,5171.53 5944.72,5171.53 v1(5957.32,5158.93)
$6N1887: R45.1 | length 108
  Bottom Layer w4: v1(5937.63,5317.4) 5955.21,5317.4 5969.8,5332 6003.8,5332 6011.8,5324 R45.1@6036.29,5324
$6N1980: R49.2 | length 76.6
  Bottom Layer w4: v1(5977,5317.41) 5977,5311.8 5987.8,5301 5997.8,5301 6005.8,5293 6030.29,5293 R49.2@6037.29,5286
$6N3980:  | length 341.9
  Bottom Layer w4: v1(4959.8,4201) 4970.8,4212 4995.8,4212 5086.8,4121 5086.8,4049 5064.8,4027 5064.8,3998.11 5036.06,3969.37
$6N4341:  | length 245.2
  Bottom Layer w4: v1(4978.8,4196) 4992.8,4196 5074.8,4114 5074.8,4053.59 5036.06,4014.85
$6N6451:  | length 421.2
  Bottom Layer w5: v1(5277.8,4303) 5277.8,4292.63 5271.8,4286.63 5271.8,4117 5301.8,4087 5349.8,4087 5355.8,4093 5355.8,4110 5366.8,4121 5398.8,4121 5443.3,4165.5 5443.3,4171.8
$6N6466:  | length 415.5
  Bottom Layer w5: v1(5256.8,4303) 5256.8,4292.63 5261.8,4287.63 5261.8,4114.25 5298.07,4077.98 5351.82,4077.98 5360.8,4069 5396.8,4069 5443.3,4115.5 5443.3,4120.7
$6N6553: R57.2 | length 47.1
  Bottom Layer w4: R57.2@5337.31,4043.53 5383.94,4043.53 5384.3,4043.9
$6N6556: R56.2 | length 132.1
  Bottom Layer w4: R56.2@5337.31,4021.53 5339.85,4019 5399.8,4019 5443.3,4062.5 5443.3,4069.5
$8N2040: D16.1 R63.2 SIM1.11 | length 139.3
  Bottom Layer w4: R63.2@6891.8,5461 6920.2,5461 D16.1@6923.8,5457.4 6975.72,5509.31 SIM1.11@6975.72,5541.73
$8N9148: R115.2 R116.1 U16.3 | length 71.3
  Bottom Layer w4: U16.3@6739.91,5340.31 6738.8,5339.2 R116.1@6738.8,5291.51 R115.2@6760.8,5291.51
$8N11462: R126.1 | length 51.8
  Bottom Layer w10: R126.1@6814.81,5250 6816.8,5252 v2(6865.8,5252)
$10N1043: C248.2 | length 123.4
  Bottom Layer w20: C248.2@5626.8,4095.7 5705.86,4095.7 5737.2,4064.36
$11N1789: C255.2 | length 131.9
  Bottom Layer w20: C255.2@6336.8,4093.7 6426.1,4093.7 6456.2,4063.6
$13N1231: R76.1 U11.8 | length 51.1
  Bottom Layer w4: R76.1@7030.8,4207.51 7033.29,4210 7044.8,4210 7062.8,4192 U11.8@7062.8,4181.39
$13N1478: U11.7 | length 130.2
  Bottom Layer w10: v2(7111.8,4288) 7140.8,4259 7140.8,4231 7112.8,4203 U11.7@7112.8,4181.39
$13N1485: U11.6 | length 131
  Bottom Layer w10: v2(7132.8,4300) 7162.8,4270 U11.6@7162.8,4181.39
$13N1600: C238.2 R65.1 | length 20.8
  Bottom Layer w5: R65.1@6096.99,6180.04 6096.99,6160.06 C238.2@6097.57,6159.49
$13N1603: C241.2 R66.1 | length 21.5
  Bottom Layer w5: C241.2@6073.57,6159.49 R66.1@6073.57,6180.98
$13N2020: C242.2 R67.2 | length 27.6
  Bottom Layer w10: R67.2@5960.29,6138 5960.29,6159.62 C242.2@5964.52,6163.85
$13N2077: C243.2 R68.2 | length 28.9
  Bottom Layer w10: R68.2@5960.29,6225 5960.29,6202.51 C243.2@5964.8,6198
ADCIN0: C106.2 R26.2 | length 161.6
  Bottom Layer w6: C106.2@5689.8,5642 5710.31,5642 R26.2@5711.8,5643.49 5716.8,5638.49 5716.8,5528.33
  Bottom Layer w7: v1(5701.42,5512.95) 5716.8,5528.33
ADCIN1: C107.2 R27.2 | length 186.5
  Bottom Layer w7: v1(5701.41,5493.27) 5704.07,5493.27 5728.8,5518 5728.8,5628 5734.29,5633.49 R27.2@5734.29,5644 5734.29,5662.49 C107.2@5735.8,5664
AGND: C108.1 C109.1 C110.1 C111.1 R28.2 | length 118
  Bottom Layer w6: v1(5602.3,5631.06) 5605.05,5628.31 C110.1@5605.05,5611.25 ; C109.1@5605.05,5589.25 C110.1@5605.05,5611.25 ; C108.1@5650.3,5583 R28.2@5650.3,5607.51 ; R28.2@5652.8,5610 R28.2@5650.3,5607.51 ; C110.1@5605.05,5611.25 5625.55,5611.25 C111.1@5625.8,5611.5 5646.31,5611.5 R28.2@5650.3,5607.51
ALDO3: C181.2 C182.2 C183.2 C184.2 | length 2670.1
  VCC w6: v1(3525.57,5315) 3539.57,5329 3557.8,5329 3580.8,5352 3580.8,5395 3574.8,5401 3574.8,5417 3589.8,5432 3589.8,5586 3612.8,5609 3759.8,5609 3792.8,5576 3792.8,5541 3812.8,5521 3812.8,5427.5 v2(3830.3,5410)
  Inner5 w18: v2(3830.3,5410) 3816.8,5410 3799.8,5427 3799.8,5476 3822.8,5499 3848.26,5499 3904.26,5555 4054.8,5555 4132.8,5633 4224.26,5633 4494.26,5903 v2(4955.8,5903)
  Bottom Layer w10: v2(5271.8,5883) 5270.8,5882 5270.8,5829 5313.8,5786 5313.8,5730 5374.8,5669 5374.8,5644 5432.8,5586 5444.8,5586 5453.8,5595 5478.8,5595 5483.8,5590 5494.8,5590 5504.8,5580 5504.8,5566 5543.93,5526.87 v2(5543.93,5512.95)
  other v2: 5256.8,5899 4979.8,5903
ALDO4: C90.2 C93.2 C108.2 C114.2 C132.1 C133.2 C161.1 C162.2 R24.2 | length 3760.5
  内层2 w10: v1(5564.8,5814) 5564.8,5805 5575.8,5794 5613.8,5794 5631.8,5812 v1(5631.8,5816)
  VCC w15: v2(5543.8,5374) 5555.8,5374 5573.7,5356.11 5594.91,5356.11 5641.8,5403 ; v1(5602.99,5197.99) 5602.99,5228.19 5612.8,5238 5633.8,5238 5641.8,5246 5641.8,5403 ; v1(5675.8,5815) 5675.8,5823 5662.8,5836 5643.8,5836 5631.8,5824 v1(5631.8,5816) 5631.8,5773 5620.8,5762 5620.8,5722 5638.8,5704 5638.8,5585 5671.48,5552.32 v1(5701.42,5552.32) 5720.8,5532.94 v2(5720.8,5484.84) 5720.8,5415 5697.8,5392 5652.8,5392 5641.8,5403
  Inner5 w18: v2@3830.4,5432.1 3830.5,5432 3848.8,5432 3867.8,5451 3867.8,5478 3915.8,5526 4060.8,5526 ; 4063.8,5528 4140.8,5605 4239.26,5605 4507.26,5873 5125.8,5873 5241.8,5757 5468.8,5757 5560.8,5665 5632.8,5665 5701.42,5596.38 v1(5701.42,5552.32)
  Bottom Layer w5: R24.2@5678.31,5491 5691.31,5478 5713.96,5478 v2(5720.8,5484.84)
  Bottom Layer w6: C108.2@5672.8,5583 5701.42,5554.38 v1(5701.42,5552.32)
  Bottom Layer w8: C114.2@5672.8,5560 5693.74,5560 v1(5701.42,5552.32)
  Bottom Layer w10: C162.2@5353.72,5206.47 5354.06,5206.81 C132.1@5391.72,5206.81 ; C132.1@5390.72,5205.81 C132.1@5391.72,5206.81 ; C90.2@5535.8,5418 C93.2@5535.8,5397 5535.8,5385.62 5543.8,5377.62 v2(5543.8,5374) ; C133.2@5602.8,5179 5602.99,5179.19 v1@5602.99,5193.19 ; v1(5602.99,5197.99) v1@5602.99,5193.19 ; C132.1@5391.72,5206.81 5397.56,5200.97 5554.02,5200.97 5573.99,5181 5590.8,5181 v1@5602.99,5193.19
  other v2: 3830.3,5432
ALDO-OUT: C103.2 | length 16.5
  Bottom Layer w7: C103.2@5582.8,5568 5582.8,5552.18 5582.98,5552 v1(5583.3,5552.32)
AP-NMI: C94.2 | length 3128
  VCC w4: v2(3614.8,5412) 3600,5426.8 3600,5569.2 v2(3619.8,5589)
  VCC w6: v2(3612.8,5350) 3612.8,5410 v2(3614.8,5412)
  Bottom Layer w4: v1(3849.8,5104) 3844.8,5109 3844.8,5169 3804.8,5209 3583.8,5209 3529.8,5263 3529.8,5288 3510.8,5307 3510.8,5326 3528.8,5344 3528.8,5351 3499.8,5380 3499.8,5410 3517.8,5428 3548.8,5428 3578.8,5398 3600.8,5398 v2(3614.8,5412) 3627.8,5425 3679.8,5425 3699.8,5445 3782.8,5445 3790.8,5453 3790.8,5632 3856.8,5698 4726.8,5698 4753.8,5725 4985.8,5725 5047.8,5663 5197.8,5663 5368.8,5492 5400.05,5492 v1(5400.8,5492.76)
  Bottom Layer w10: v1(5400.8,5492.76) 5419.56,5492.76 C94.2@5420.8,5494
AP-RESET:  | length 3196.6
  VCC w5: v2(3591.8,5413) 3590.8,5412 3590.8,5279 3669.8,5200 3892.8,5200 v2(3896.8,5204)
  VCC w6: v1(3961.8,5075) 3961.8,5053 4023.8,4991 v2(4218.8,4991)
  Bottom Layer w4: v2(3591.8,5413) 3614.8,5436 3677.8,5436 3694.8,5453 3773.8,5453 3781.8,5461 3781.8,5641 3849.8,5709 4719.8,5709 4748.8,5738 4989.8,5738 5053.8,5674 5202.8,5674 5374.8,5502 5390.8,5502 5394.8,5506 5396.77,5506 5403.77,5513 5473.8,5513 5492.8,5494 v1@5502.8,5494
  Bottom Layer w5: v2(3896.8,5204) 3896.8,5140 v1(3961.8,5075)
  other v1: 5504.8,5493
AP-WAKE-BT:  | length 1955.2
  Inner5 w4: v1(3991.8,5843) 4014.8,5820 4081.8,5820 4190.8,5929 5098.8,5929 5249.8,5778 5489.8,5778 5539.8,5728 5598.8,5728 5715.42,5611.39 v1(5760.78,5611.39)
BLDO1: C165.2 C166.2 C171.2 C172.2 | length 3554.6
  VCC w15: 5437.8,5570 5455.8,5552 5543.8,5552 v2(5562.8,5571)
  VCC w20: v2(3830.3,5454) 3848.8,5454 3872.45,5477.65 3872.45,5593 3892.45,5613 4303.8,5613 v2(4450.8,5760) 4518.8,5828 5183.8,5828 5437.8,5574
  Inner5 w10: v2(5562.8,5571) 5566.8,5575 5585.8,5575 5601.8,5559 5601.8,5545 5613.8,5533 5719.8,5533 5739.8,5513 5757.8,5513 ; v1(5780.8,5534) 5780.8,5528.34 5765.46,5513 ; v2(5818.8,5218) 5823.8,5213 5844.8,5213 5858.8,5227 5858.8,5312 5876.8,5330 5876.8,5421.14 5863.95,5434 5849.8,5434 5801.8,5482 5788.8,5482 5757.8,5513 ; v1(5819.52,5529.95) 5819.52,5525.72 5806.8,5513 5765.46,5513 ; 5757.8,5513 5765.46,5513
  Bottom Layer w10: C172.2@5543.8,5604 5543.8,5584 5556.8,5571 v2(5562.8,5571) ; v2(5818.8,5218) 5814.8,5214 C166.2@5814.8,5198 C171.2@5836.8,5198 ; v1(5819.52,5529.95) 5819.8,5530.23 C165.2@5819.8,5553
  Bottom Layer w20: v2(3877.8,5869) 3896.8,5869 4022.8,5743 v2(4294.8,5743) 4311.8,5760 v2(4450.8,5760)
BLDO2: C134.1 C135.2 C137.2 C138.2 C141.2 | length 1690.8
  内层4 w20: v2(3830.3,5476) 3844.3,5490 v2(3914.8,5490) 3941.8,5490 4023.8,5408 4564.8,5408 4600.65,5443.84 v3(4624.81,5443.84)
  Bottom Layer w6: v2(3914.8,5490) 3891.8,5467 3891.8,5246 3914.8,5223 3914.8,5145 3976.8,5083 v1(3976.8,5060)
  Bottom Layer w8: v3(4872.1,5183.24) 4888.8,5199.95 4888.8,5228.97 4940.72,5228.97 4967.72,5201.97 C138.2@4967.72,5186.97
  Bottom Layer w10: v3@4614.2,5174.49 v3(4615.72,5174.49) ; v3(4624.81,5443.84) 4626.68,5441.97 4651.72,5441.97 4666.81,5426.89 4666.81,5409.07 4675.91,5399.97 4700.72,5399.97 4717.49,5416.74 v3(4717.8,5416.74) ; C137.2@4738.72,5207.97 4738.72,5200.23 v3(4748.32,5190.63) ; C135.2@4848.72,5162.97 4868.99,5183.24 v3(4872.1,5183.24) ; v3(4967.72,5160.97) C138.2@4967.72,5186.97
  other v3: 4872.72,5440.97 4968.72,5442.72
BLDO3: C104.2 C185.2 C186.2 C187.2 C188.2 C201.2 C202.2 C208.2 C209.2 R127.1 R128.1 | length 3082.7
  内层2 w10: v2(5839.8,5473) 5884.8,5473 5905.8,5494 6035.8,5494 6077.8,5536 v2(6091.8,5536)
  VCC w15: v2(3830.3,5520) 3849.8,5539.5 3849.8,5604 3882.8,5637 4288.8,5637 4506.8,5855 5187.8,5855 5451.8,5591 5516.8,5591 v1(5523.8,5584)
  Bottom Layer w5: C187.2@5843.8,5332 5855.8,5332
  Bottom Layer w10: C202.2@5511.58,5597.22 5511.58,5596.22 v1(5523.8,5584) ; v2(5839.8,5235) 5841.8,5233 C201.2@5857.8,5233 ; R127.1@6041.31,5562 R128.1@6041.31,5539 6088.8,5539 v2(6091.8,5536)
  Bottom Layer w15: v1(5523.8,5584) 5523.8,5574 5563.8,5534 5563.8,5503 5572.8,5494 5604.8,5494 5644.8,5454 5707.58,5454 5727.58,5434 C208.2@5738.8,5434 5839.8,5434
  Bottom Layer w18: v2(5839.8,5235) 5834.8,5240 C185.2@5834.8,5253 C186.2@5834.8,5272 5834.8,5284 v2(5822.8,5296) 5826.8,5296 5861.8,5331 ; v2(5839.8,5473) C104.2@5839.8,5452 5839.8,5434 v2(5858.8,5415) 5869.8,5415 5880.8,5404 5880.8,5357 5855.8,5332
BT-RESETN:  | length 502.2
  Bottom Layer w4: v2(4347.97,6026.72) 4458.08,6026.72 4715.8,5769 4720.8,5769 v1(4736.8,5753)
BT-WAKE-AP:  | length 1989.9
  Inner5 w4: v1(4010.8,5850) 4010.8,5842 4022.8,5830 4075.8,5830 4188.8,5943 5100.8,5943 5253.8,5790 5492.8,5790 5543.8,5739 5603.8,5739 5717.8,5625 5766.8,5625 5774.8,5617 5774.8,5605.71 v1(5760.78,5591.69)
CAN-RX0: U11.4 | length 4571.5
  内层2 w4: v2(5108.8,5734) 5123.8,5719 5132.8,5719 5170.8,5681 5284.8,5681 5362.8,5603 5362.8,5482.58 5453.38,5392 5494.18,5392 5503.8,5382.37 v1(5503.8,5373)
  内层4 w4: v2(5060.8,6013) 5109.8,6062 5385.8,6062 5587.8,5860 5719.8,5860 5773.8,5806 6711.8,5806 6814.8,5703 6814.8,5575 6756.8,5517 6756.8,4762 7041.8,4477 7090.8,4477 7202.8,4365 v2(7202.8,4307)
  Bottom Layer w4: v2(5060.8,6013) 5060.8,5985 5069.8,5976 5069.8,5827 5115.8,5781 5115.8,5741 v2(5108.8,5734) ; v2(7202.8,4307) 7212.8,4317 U11.4@7212.8,4392.61
CAN-TX0: U11.1 | length 4269.9
  内层2 w4: v2(5131.8,5735) 5132.15,5735 5176.15,5691 5291.8,5691 5372.8,5610 5372.8,5486 5457.65,5401.15 5500.65,5401.15 5523.8,5378 v1(5523.8,5373)
  内层4 w4: v2(5081.8,6012) 5119.8,6050 5378.8,6050 5579.8,5849 5714.8,5849 5767.8,5796 6705.8,5796 6802.8,5699 6802.8,5581 6742.8,5521 6742.8,4758 7040.8,4460 v2(7055.8,4460)
  Bottom Layer w4: v2(5081.8,6012) 5081.8,5833 5131.8,5783 v2(5131.8,5735) ; v2(7055.8,4460) 7062.8,4453 U11.1@7062.8,4392.61
CLDO1: C163.2 C164.2 C225.1 C226.2 C227.2 | length 2930.5
  Bottom Layer w20: v1(3828.8,5562) 3864.8,5526 3864.8,5126 4133.8,4857 4700.8,4857 4722.8,4835 v1(4722.8,4819) 4722.8,4735 4750.8,4707 4943.03,4707 ; v1(4944.8,4771) 4944.8,4708.78 4943.03,4707 ; v1(5740.78,5178.3) 5740.78,5067.98 5705.8,5033 5705.8,4953 5568.8,4816 5092.8,4816 4983.8,4707 4943.03,4707
CLDO2: C91.2 | length 4483.4
  VCC w10: v2(3830.3,5584) 3830.3,5597.5 3777.43,5650.37 3624.18,5650.37 3556.43,5582.63 3556.43,5535.58 3467.63,5446.78 3467.63,4398.17 3614.8,4251 4154.8,4251 4172.8,4269 4336.96,4269 4571.96,4504 4675.8,4504 4793.8,4622 4793.8,4746 4841.19,4793.39 5580.19,4793.39 5763.8,4977 v2(5763.8,5110)
  Bottom Layer w10: v2(5763.8,5110) 5781.8,5128 5781.8,5154 C91.2@5788.8,5161
CLDO3: C102.2 C228.1 C229.2 C230.2 C234.1 C235.2 C236.2 D20.1 R73.2 R74.2 R75.2 SIM1.4 U18.8 | length 12288.6
  VCC w10: v2(5555.4,6051.1) 5597.29,6093 5784.8,6093 5829.8,6138 5964.8,6138 6026.8,6200 6321.8,6200 6413.8,6292 6931.8,6292 7068.8,6155 7142.8,6155 7161.8,6136 7161.8,6017 7146.8,6002 7146.8,5534.4 v1(7105.8,5493.4)
  VCC w15: v2(3830.3,5628) 3842.8,5628 3872.8,5658 4275.8,5658 4497.8,5880 5192.8,5880 5373.8,5699 5421.8,5699 5454.8,5666 5563.13,5666 5581.8,5647.33 5581.8,5592 5602.8,5571 5602.8,5532.82 v2@5622.68,5512.95
  VCC w20: 3443.8,5467 3532.8,5556 3532.8,5605 3599.55,5671.75 3786.56,5671.75 v2(3830.3,5628) ; v2(6576.8,4584) 6577.8,4585 v2(6596.88,4585) 6886.8,4585 6925.8,4624 6925.8,4910 6872.8,4963 6872.8,5006 7088.8,5222 7088.8,5476.4 v1(7105.8,5493.4)
  VCC w25: v2(4880.8,4766) 4880.8,4538 4879.8,4537 5629.8,4537 v2(5686.8,4480) v2(5704.8,4480)
  VCC w30: 3443.8,5467 3438.8,5462 3438.8,4377 3588.8,4227 4337.8,4227 v2(4468.8,4358) 4583.8,4473 4815.8,4473 4879.8,4537
  Inner5 w20: v2(5686.8,4480) v2(5704.8,4480) 5720.8,4480 5751.8,4449 6115.8,4449 6251.8,4585 v2(6596.88,4585)
  Bottom Layer w6: v2(4880.8,4766) 4896.55,4750.25 C229.2@4901.55,4750.25 C235.2@4920.55,4750.25 ; v2(7090.3,5301) C228.1@7090.3,5318 C234.1@7090.3,5341
  Bottom Layer w10: C230.2@4872.8,4749 4872.8,4758 v2(4880.8,4766) ; R75.2@5542.8,6038.51 v2(5555.4,6051.1) 5573.29,6069 U18.8@5580.8,6069 ; U18.8@5576.8,6065 U18.8@5580.8,6069 ; U18.8@5585.03,6069 U18.8@5580.8,6069 ; C102.2@5609.8,5513 v2(5622.62,5513) ; R74.2@5950.8,5989.51 5950.8,6066 5903.31,6113.49 R73.2@5903.31,6135 5903.31,6143.49 5893.8,6153 5863.8,6153 5802.8,6092 5603.8,6092 U18.8@5580.8,6069 ; D20.1@7070.8,5458.4 v1(7105.8,5493.4) 7105.8,5635 7135.8,5665 7135.8,5709 7202.2,5775.4 SIM1.4@7211.94,5775.4
CPUSLDO: C13.1 C14.1 | length 1841
  Bottom Layer w8: v2(3917.8,5583) 3917.8,5586 3962.8,5631 5178.8,5631 5333.8,5476 5333.8,5453 5346.8,5440 5360.8,5440 5381.8,5461 5572.8,5461 5597.8,5436 5615.67,5436 v2(5622.67,5443)
CPUX-RX:  | length 4663.1
  内层2 w4: 4032.8,6343 4082.8,6293 4082.8,6188 4117.8,6153 5823.8,6153 5849.8,6127 6556.8,6127 6585.8,6156 6731.8,6156 v2@6772.8,6115
  VCC w4: v2(6271.8,5252) 6271.8,5342 6487.8,5558 6487.8,6031 6567.8,6111 6612.8,6111 6637.8,6086 6756.8,6086 6773,6102.2 v2(6773,6114.8)
  内层4 w4: v1(5800.16,5119.25) 5833.9,5153 5923.8,5153 5943.8,5173 6073.8,5173 6119.8,5219 6230.8,5219 6263.8,5252 v2(6271.8,5252)
CPUX-TX:  | length 4472.8
  内层2 w4: 3932.8,6343 3985.8,6290 3985.8,6210 4004.8,6191 4062.8,6191 4110.8,6143 5816.8,6143 5843.8,6116 6562.8,6116 6592.8,6146 6628.8,6146 6644.59,6130.21 v2(6644.59,6111.36)
  VCC w4: v2(6251.8,5263) 6259.8,5271 6259.8,5351 6474.8,5566 6474.8,6037 6559.8,6122 6618.8,6122 6629.44,6111.36 v2(6644.59,6111.36)
  内层4 w4: v1(5800.16,5138.93) 5824.23,5163 5917.8,5163 5938.8,5184 6068.8,5184 6113.8,5229 6223.8,5229 6251.8,5257 v2(6251.8,5263)
CPVDD: C105.2 | length 28
  Bottom Layer w6: v1(5523.57,5631.06) 5523.57,5658.76 C105.2@5523.8,5659
CPVEE: C115.2 | length 91.7
  Bottom Layer w6: v1(5484.8,5633) 5502.8,5651 C115.2@5502.8,5658.5 5504.8,5656.5 5504.8,5625 5518.42,5611.38 v1(5523.56,5611.38)
CTP-INT: FPC1.35 | length 2652.9
  Inner5 w5: v1(4309.8,4394) 4322.8,4407 4322.8,4613 4447.8,4738 4997.8,4738 5101.8,4842 5720.8,4842 5772.8,4894 v1(5815.8,4894)
  Bottom Layer w5: FPC1.35@3538.78,4277.99 3575.8,4277.99 3623.8,4326 4038.8,4326 4106.8,4394 v1(4309.8,4394)
CTP-RST: FPC1.36 | length 2973
  内层2 w5: v1(4293.8,4376) 4320.8,4376 4357.8,4413 4357.8,4493 4375.8,4511 4375.8,4732 4526.8,4883 4765.98,4883 4765.98,4882.83 4802.8,4846 4841.8,4846 4863.8,4824 4863.8,4802 4872.8,4793 4893.8,4793 4919.8,4819 4972.8,4819 5009.8,4782 5410.8,4782 5511.8,4883 5700.8,4883 5782.8,4965 5782.8,5002 5800.15,5019.34 v1(5800.15,5099.56)
  Bottom Layer w5: FPC1.36@3538.78,4258.31 3580.11,4258.31 3631.8,4310 4049.8,4310 4115.8,4376 v1(4293.8,4376)
CTP-SCK: FPC1.37 | length 2659.1
  Inner5 w5: v1(4276.8,4359) 4280.8,4355 4299.8,4355 4336.8,4392 4336.8,4605 4452.8,4721 5006.8,4721 5110.8,4825 5725.8,4825 5776.8,4876 v1(5805.8,4876)
  Bottom Layer w5: FPC1.37@3538.78,4238.62 3583.43,4238.62 3639.8,4295 4061.8,4295 4125.8,4359 v1(4276.8,4359)
CTP-SDA: FPC1.38 | length 2647.2
  Inner5 w5: v1(4259.8,4341) 4263.8,4337 4304.8,4337 4350.8,4383 4350.8,4597 4458.8,4705 5013.8,4705 5116.8,4808 5739.8,4808 v1(5791.8,4860)
  Bottom Layer w5: FPC1.38@3538.78,4218.94 3584.74,4218.94 3644.8,4279 4072.8,4279 4134.8,4341 v1(4259.8,4341)
DCDC1: C36.1 C37.1 C38.1 C39.1 C40.1 C41.1 C288.2 C289.2 | length 182.7
  Bottom Layer w10: C40.1@5640.8,5339.5 5660.3,5339.5 C37.1@5660.55,5339.25 C36.1@5679.55,5339.25 5681.73,5337.08 v2(5681.73,5316.1) 5690.3,5307.52 5690.3,5304.99 ; v2(5681.73,5276.73) 5690.3,5285.3 5690.3,5287.83 ; C38.1@5699.34,5338.61 5701.41,5336.53 C38.1@5701.41,5336 ; v2(5701.41,5276.73) 5690.3,5287.83 ; C39.1@5718.91,5338.47 5716.45,5336 C38.1@5701.41,5336 ; 5690.3,5287.83 C41.1@5690.3,5297 5690.3,5304.99 ; 5690.3,5304.99 v2(5701.41,5316.1) C38.1@5701.41,5336
  other v1: 3809.8,5276 3789.8,5284.37 3809.8,5296.99 3789.8,5309 3809.8,5320.54 3789.8,5337
DCDC2: C47.1 C48.1 C49.1 C50.1 C57.1 C58.1 C67.1 C68.1 C75.1 C76.1 C77.1 C78.1 C211.2 C213.2 C214.2 C215.2 C216.2 | length 429.2
  Bottom Layer w6: C213.2@5911.8,5513 C214.2@5932.8,5513 ; C214.2@5933.8,5514 C214.2@5932.8,5513 ; 5937.3,5492 5937.3,5508.5 C214.2@5932.8,5513
  Bottom Layer w10: v1(5760.8,5413) 5766.8,5413 5779.3,5400.5 C47.1@5779.3,5392 5779.8,5391.5 v2(5779.8,5374) ; v1(5760.8,5455) 5760.8,5472.5 C77.1@5761.55,5473.25 ; C50.1@5779.8,5309.5 5780.8,5308.5 v2(5780.8,5296) v2(5780.8,5278) 5800.3,5278 C48.1@5800.8,5277.5 v2(5800.8,5296) C49.1@5800.8,5309.5 ; C78.1@5780.55,5473.25 5780.8,5473 v1(5780.8,5454) ; C76.1@5799.55,5473.25 C76.1@5799.8,5473 ; v1(5799.8,5454) C76.1@5799.8,5473 ; C75.1@5818.55,5473.25 5818.3,5473 C76.1@5799.8,5473 ; C58.1@5911.3,5369 5914.8,5372.5 v2(5914.8,5375.16) 5914.8,5387.5 C57.1@5911.3,5391 C67.1@5911.3,5413 C68.1@5911.3,5433 C215.2@5911.3,5452 C216.2@5911.3,5472 C211.2@5911.3,5491.5 ; C213.2@5911.8,5513 C211.2@5911.8,5492 C211.2@5911.3,5491.5 ; 5937.3,5492 5936.8,5491.5 C211.2@5911.3,5491.5
  other v1: 3566.8,5755 3587.8,5755 3627.8,5763 3649.8,5763 3627.8,5782 3648.8,5782
  other v2: 5839.8,5355 5760.8,5356
DCDC3: C116.1 C117.1 C118.2 C119.2 C120.2 C121.2 C122.2 C123.2 C124.2 C125.2 C126.2 C127.2 C128.2 C129.2 C130.2 C142.1 C143.1 C144.2 C145.2 C151.2 C152.2 C153.2 C154.2 C155.2 C156.2 R38.2 R39.2 R40.2 | length 3548
  内层4 w3: v3(4785.72,5119.97) 4816.8,5125 4826.8,5120 4826.8,5109 4823.44,5072
  内层4 w4: v3(4784.72,5068.97) 4787.75,5072 4823.44,5072 4855.69,5072 v3(4871.72,5055.97)
  内层4 w10: v1(3717.8,5590) 3710.8,5597 3710.8,5753 3760.8,5803 3862.8,5803 3890.8,5775 3975.8,5775 4096.8,5654 5108.8,5654 5391.8,5371 5465.8,5371 5481.38,5355.42 v3(5622.35,5355.42)
  Bottom Layer w8: C156.2@4686.72,5348.97 4686.72,5339.96 v3(4694.27,5332.41) ; v3(4801.72,5424.97) v3(4822.72,5424.97) ; C121.2@4931.72,5345.97 4931.72,5360.73 v3(4935.96,5364.97) ; C125.2@4952.59,5598.2 4952.59,5604.84 v3(4954.72,5606.97)
  Bottom Layer w10: v3(4591.72,5385.97) 4602.75,5397 4644.78,5397 v3(4649.77,5392.01) ; C116.1@4652.3,5060.67 4675.6,5083.97 4684.6,5083.97 v3(4685.06,5084.43) ; C117.1@4666.8,5178.5 v3(4686.72,5186.97) ; v3(4682.81,5465.47) 4684.65,5467.31 C130.2@4722.92,5467.31 ; C143.1@4689.72,5573.97 v3(4715.72,5573.97) ; v3(4718.72,5295.97) 4736.88,5295.97 C142.1@4741.72,5300.81 ; R40.2@4756.01,5072.13 4781.56,5072.13 v3(4784.72,5068.97) ; C124.2@4762.56,5115.97 4781.72,5115.97 v3(4785.72,5119.97) ; v3(4780.64,5423.21) 4801.17,5402.68 4806.92,5402.68 4806.92,5419.77 v3(4801.72,5424.97) ; v3(4780.72,5556.97) 4780.72,5523.97 v3(4782.72,5521.97) ; v3(4781.37,5219.8) 4797.88,5203.29 4797.88,5195.17 v3(4784.65,5181.94) ; v3(4834.72,5608.97) 4846.72,5596.97 C144.2@4857.88,5596.97 ; R39.2@4867.72,5032.81 4867.72,5051.97 v3(4871.72,5055.97) ; v3(4872.72,5109.97) C118.2@4888.72,5109.97 ; v3(4891.41,5028.72) 4897.06,5023.07 C152.2@4897.06,5006.06 ; v3(4998.72,5120.97) 4998.72,5126.97 5012.88,5141.13 C123.2@5022.72,5141.13 ; C145.2@5021.22,5501.97 5021.22,5521.47 v3(5022.72,5522.97) ; C122.2@5047.56,5200.97 5047.56,5196.13 v3(5061.72,5181.97) ; R38.2@5660.8,5155.51 5660.8,5216.7 v3(5661.72,5217.62)
  Bottom Layer w12: C154.2@5603.8,5316 v3(5622.35,5316.05) ; C128.2@5603.8,5336 5622.08,5336 5622.35,5335.73 v3(5622.35,5355.42) ; C155.2@5621.8,5202 5622.35,5202.55 v3(5622.35,5217.62) ; v3(5622.35,5256.99) 5617.36,5252 C126.2@5604.3,5252 ; v3(5622.36,5296.36) 5622,5296 5603.8,5296 5603.8,5275 5603.8,5252.5 C126.2@5604.3,5252 ; C119.2@5641.8,5202 5642.03,5202.23 v3(5642.03,5217.62) ; C129.2@5681.8,5201 5681.8,5217.22 v3(5681.41,5217.62) ; v3(5700.8,5237) 5701.09,5236.71 v3(5701.09,5217.62) ; v3(5701.1,5197.94) v3(5701.09,5217.62) ; C126.2@5604.3,5252 5604.3,5235.66 v3(5622.35,5217.62) ; v3(5622.35,5217.62) v3(5642.03,5217.62) ; v3(5642.03,5217.62) v3(5661.72,5217.62) v3(5681.41,5217.62) ; v3(5681.41,5217.62) v3(5701.09,5217.62)
  other v1: 3788.82,5693 3808.8,5714 3769.8,5715 3788.8,5715 3770.8,5742 3789.8,5742
  other v3: 4726.64,5025.97 4935.72,5056.97 4619.64,5112.97 4903.65,5164.94 4837.72,5181.97 4871.88,5212.83 4621.41,5237.13 4623.72,5267.97 4935.64,5270.97 5000.72,5273.97 5622.36,5335.73 4626.72,5338.97 4997.8,5357 5040.72,5406.97 4935.72,5443.97 4838.72,5485.97 4619.72,5518.97 4811.72,5545.97 4733.08,5603.19
DSP-UART-RX:  | length 782.9
  Bottom Layer w4: v2(5425.8,5652) 5427.8,5654 5427.8,5688 5418.8,5697 5405.41,5697 5384.8,5717.61 5384.8,5747 5379.8,5752 5379.8,5811 5453.8,5885 5453.8,6184 5483.8,6214 5483.8,6289 5532.8,6338 5532.8,6343
DSP-UART-TX:  | length 544.6
  Bottom Layer w4: v2(5366.8,5734) 5366.8,5816 5442.8,5892 5442.8,6233 5432.8,6243
EDP-AUXN:  | length 481.5
  内层2 w5: v1(5276.8,4476.5) 5268.8,4468.5 5268.8,4460 5273.8,4455 5286.08,4455 5291.08,4460 5291.08,4471 5296.08,4476 5301.08,4476 5306.08,4471 5306.08,4460 5311.08,4455 5316.08,4455 5321.08,4460 5321.08,4471 5326.08,4476 5331.08,4476 5336.08,4471 5336.08,4460 5341.08,4455 5370.8,4455 5380.43,4445.38 5608.43,4445.38 5641.8,4478.75 v1(5641.8,4487)
EDP-AUXP:  | length 440.9
  内层2 w5: v1(5255.8,4476.5) 5259.79,4472.52 5259.79,4455.27 5271.05,4444 5369.05,4444 5376.69,4436.36 5612.16,4436.36 5647.8,4472 5653.8,4472 v1(5654.8,4471)
EDP-HPD:  | length 1454.6
  内层2 w5: v1(5333.8,4493) 5594.8,4754 5932.8,4754 5953.8,4775 5953.8,4826 6097.8,4970 6097.8,5084 6062.55,5119.25 v1(5996.37,5119.25)
  Bottom Layer w5: v1(5315.5,4334) 5309.8,4328.3 5309.8,4226 5325.8,4210 5333.8,4210 5351.8,4192 5351.8,4166 5371.6,4146.2 5384.3,4146.2
EDP-TX0N:  | length 921.6
  内层2 w5: v1(5539.8,4477) 5539.8,4486.37 5545.4,4491.97 5545.4,4510.35 5663.07,4628.02 6182.09,4628.02 6246.8,4692.73 6246.8,4742 6263.8,4759 6278.8,4759 6289.88,4747.92 v1(6294.93,4747.92)
EDP-TX0P:  | length 901
  内层2 w5: v1(5560.8,4477) 5560.8,4485.58 5554.41,4491.97 5554.41,4506.61 5666.8,4619 6185.8,4619 6256.8,4690 6256.8,4738 6267.8,4749 6275.8,4749 6280.8,4744 6280.8,4735.21 v1(6278.67,4733.08)
EDP-TX1N:  | length 1047.6
  内层2 w5: v1(5479.8,4478) 5479.8,4486.37 5486.4,4492.97 5486.4,4503.35 5645.07,4662.02 5992.82,4662.02 6043.8,4713 6043.8,4785 6150.82,4892.02 6235.54,4892.02 6276.55,4851 v1(6285.8,4851)
EDP-TX1P:  | length 1027.3
  内层2 w5: v1(5501.8,4477) 5501.8,4486.58 5495.41,4492.97 5495.41,4499.61 5648.8,4653 5997.8,4653 6052.8,4708 6052.8,4781.25 6154.55,4883 6231.8,4883 6272.8,4842 v1(6272.8,4836)
EDP-TX2N:  | length 1011.4
  内层2 w5: v1(5427.8,4478) 5427.8,4488.37 5433.3,4493.87 5433.3,4504.24 5626.07,4697.02 5975.82,4697.02 6011.8,4733 6011.8,4794.73 6141.08,4924.02 6173.82,4924.02 6181.8,4932 6195.8,4932 v2(6200.8,4937)
EDP-TX2P:  | length 1010.2
  内层2 w5: v1(5447.8,4478) 5447.8,4488.37 5442.31,4493.87 5442.31,4500.51 5629.8,4688 5979.8,4688 6020.8,4729 6020.8,4790.98 6144.82,4915 6179.8,4915 6186.8,4922 v2(6216.8,4922)
EDP-TX3N:  | length 1051.9
  内层2 w5: v1(5368.8,4476) 5368.8,4486.37 5374.8,4492.37 5374.8,4498.6 5380.21,4504.01 5380.21,4511.08 5387.28,4518.15 5394.35,4518.15 5401.42,4525.22 5401.42,4532.3 5408.49,4539.37 5415.56,4539.37 5422.63,4546.44 5422.63,4553.51 5429.7,4560.58 5436.77,4560.58 5443.85,4567.65 5443.85,4574.72 5450.92,4581.79 5457.99,4581.79 5609.21,4733.02 5956.82,4733.02 5978.8,4755 5978.8,4806.75 6138.05,4966 6149.8,4966 v2(6157.8,4974)
EDP-TX3P:  | length 1037.1
  内层2 w5: v1(5389.8,4476) 5389.8,4486.37 5383.81,4492.37 5383.81,4494.87 5612.94,4724 5960.8,4724 5987.8,4751 5987.8,4803 6141.8,4957 6167.8,4957 v2(6174.8,4964)
EMMC-VDDI: C231.1 C232.2 C233.2 | length 69.7
  Bottom Layer w10: v1(4984.8,4897) 4993.8,4906 C232.2@5005.8,4906 ; C233.2@5005.8,4884 C232.2@5005.8,4906 ; C231.1@5005.8,4929 C232.2@5005.8,4906
FEL:  | length 2809.3
  内层2 w6: v2(4072.8,5792) 4093.8,5771 4093.8,5569 v2(4218.8,5444)
  VCC w6: v2(4072.8,5792) 4116.8,5792 4201.8,5707 4296.8,5707 4527.8,5938 5189.8,5938 5285.8,5842 5621.8,5842 5633.8,5854 5669.8,5854 5692.8,5831 5692.8,5719 5750.8,5661 5825.8,5661 5857.8,5629 5857.8,5546 5899.8,5504 5899.8,5441.81 5946.45,5395.16 v1(5957.32,5395.16)
GM0_DVDD10:  | length 789.5
  Bottom Layer w23: v1(5757.8,4521) v1(5757.8,4499) 5757.8,4487 5845.8,4399 5845.8,4313.21 ; v1(5796.69,4294.89) 5827.48,4294.89 5845.8,4313.21 ; 5847.8,4403 5884.8,4440 6007.8,4440 6069.8,4502 v1(6069.8,4512.5) ; v1(5903.8,4214) 5903.8,4245 ; v1(5983.2,4215) 5953.2,4245 5903.8,4245 ; 5845.8,4313.21 5845.8,4303 5903.8,4245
